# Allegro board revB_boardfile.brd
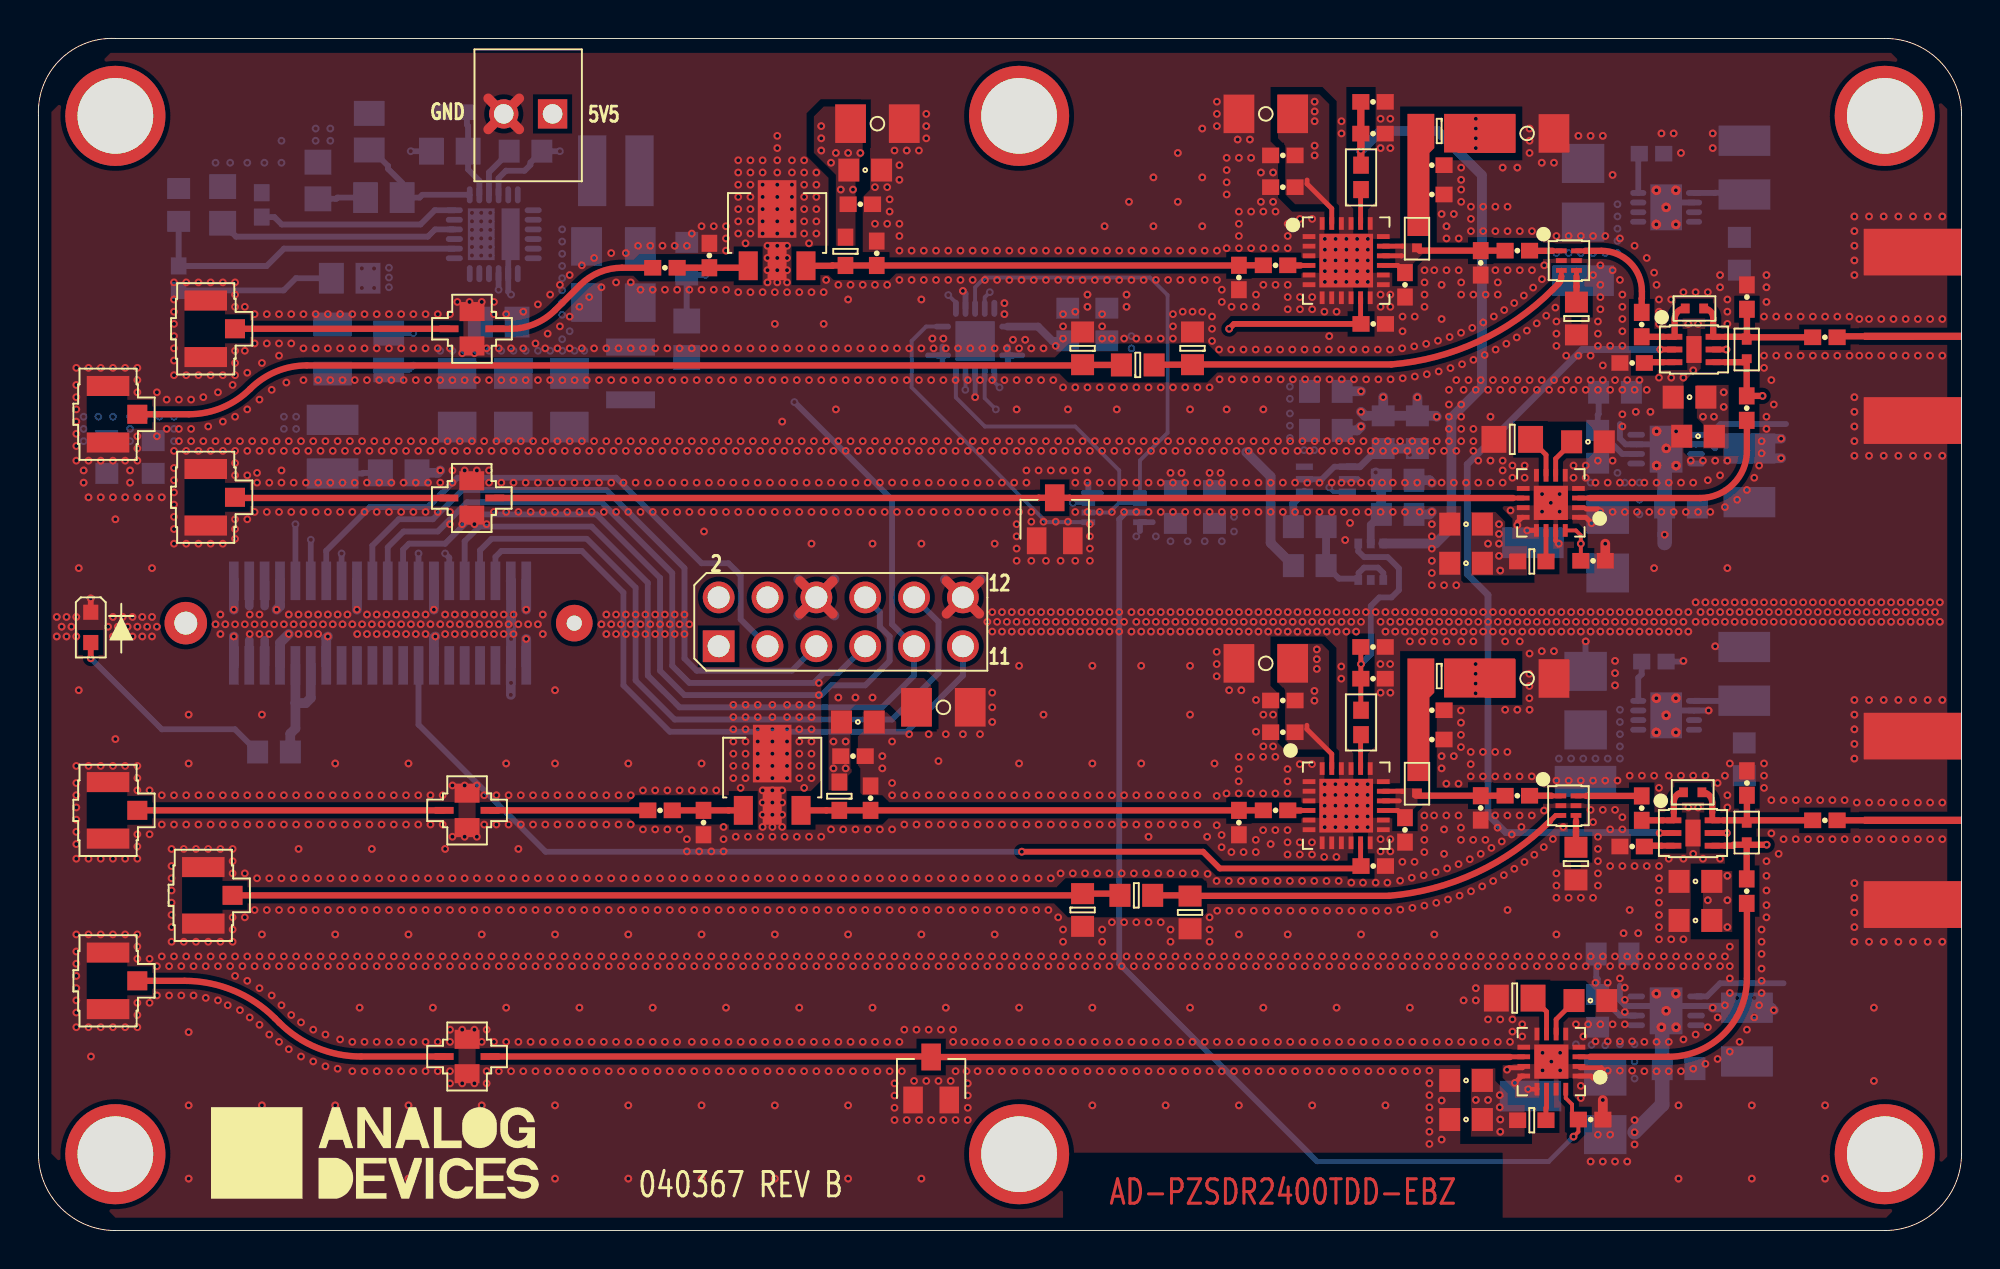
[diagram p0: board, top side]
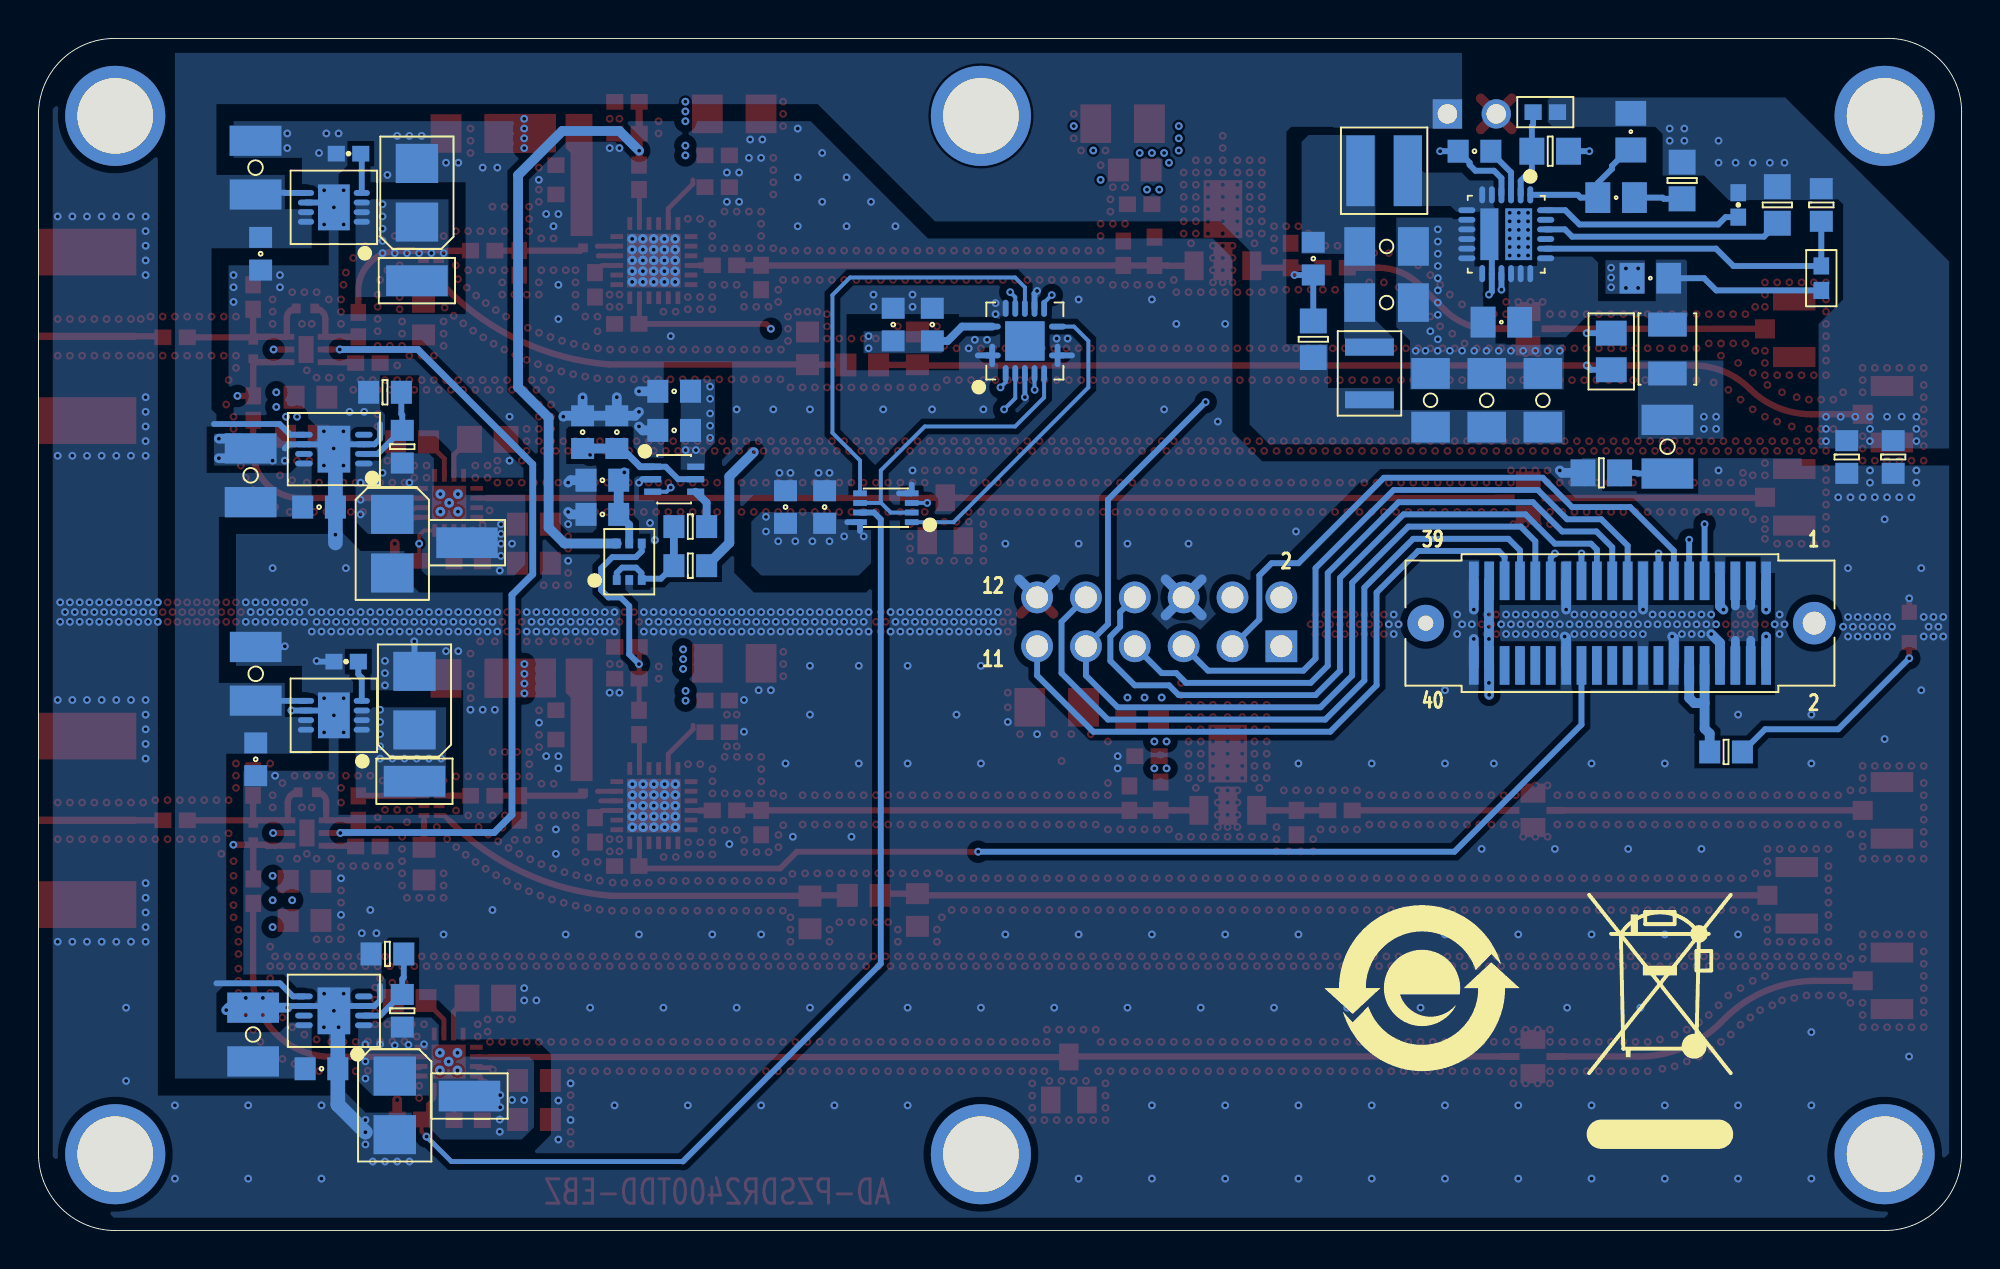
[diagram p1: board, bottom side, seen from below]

Outline 99.99 x 61.99 mm; copper layers: TOP, L2_GND, L3_PWR, BOTTOM. Coordinates in mm from the lower left corner of the outline.
Outline path: 0,58 0,4 arc(1.17,1.17) 4,0 96,0 arc(98.82,1.17) 99.99,4 99.99,58 arc(98.84,60.84) 96,61.99 4,61.99 arc(1.12,60.88) 0,58

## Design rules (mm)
net group RF_GPIO0_5V: nets RF_GPIO0_5V UNNAMED_2_ADHMC921_I79_VEN
net group RF_GPIO1_5V: nets RF_GPIO1_5V UNNAMED_3_ADHMC921_I94_VEN

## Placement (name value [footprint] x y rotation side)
AMP1  HK-1-G  [CNTP1206]  80.32 49.4 0 bottom
AMP2  HK-1-G  [CNTP1206]  80.44 23.37 0 bottom
C1  8200PF  [C0603]  80.7 11.96 0 top
C2  1000pF  [C0402]  83.87 56 0 bottom
C3  8200PF  [C0603]  80.57 41.02 0 top
C4  1UF  [C0603]  61.15 37.63 90 bottom
C5  2.2pF  [C0402]  32.32 21.85 0 top
C6  1.3pF  [C0402]  34.58 21.22 270 top
C7  10uF  [C1206]  47.05 27.21 0 top
C8  10000pF  [C0603]  42.61 26.45 0 top
C9  100PF  [C0402]  42.35 24.67 0 top
C10  1UF  [C0603]  74.23 7.81 180 top
C11  10000pF  [C0603]  74.23 5.77 180 top
C12  2pF  [C0402]  43.27 22.49 90 top
C13  3.3pF  [C0402]  62.42 21.22 270 top
C14  100PF  [C0402]  80.71 5.77 0 top
C15  2.7pF  [C0402]  64.32 21.85 0 top
C16  2.2uF  [C1206]  63.82 29.5 0 top
C17  1000pF  [C0402]  64.71 27.57 0 top
C18  100PF  [C0402]  64.71 25.92 0 top
C19  4.7uF  [C0805H60]  16.18 49.53 0 bottom
C20  22uF  [C1210]  88.71 55.28 90 bottom
C21  22uF  [C1210]  88.96 39.28 90 bottom
C22  1UF  [C0603]  88.44 50.8 270 bottom
C23  1UF  [C0603]  85.41 37.63 180 bottom
C24  100PF  [C0402]  69.4 18.96 0 top
C25  1000pF  [C0402]  69.39 30.35 0 top
C26  10uF  [C3528]  80.32 53.97 90 bottom
C27  10uF  [C3528]  81.6 35.72 270 bottom
C28  100PF  [C0402]  69.39 28.7 0 top
C29  4pF  [C0402]  71.06 20.84 270 top
C30  2.2uF  [C1206]  77.41 28.71 0 top
C31  1000pF  [C0402]  72.45 27.06 0 top
C32  100PF  [C0402]  72.45 25.53 0 top
C33  1.5pF  [C0402]  74.99 21.98 270 top
C34  100PF  [C0402]  76.9 22.61 0 top
C35  330pF  [C0402]  83.36 21.97 270 top
C36  1.8PF  [C0402]  82.87 19.97 180 top
C37  1UF  [C0603]  86.16 16.13 180 top
C38  10000pF  [C0603]  86.16 18.16 180 top
C39  330pF  [C0402]  88.83 17.65 90 top
C40  0.7pF  [C0402]  88.84 23.27 90 top
C41  330pF  [C0402]  92.89 21.33 0 top
C42  2.2pF  [C0402]  32.57 50.07 0 top
C43  1.3pF  [C0402]  34.89 50.71 90 top
C44  10uF  [C1206]  43.62 57.56 0 top
C45  10000pF  [C0603]  42.99 55.15 0 top
C46  100PF  [C0402]  42.73 53.37 0 top
C47  1UF  [C0603]  74.23 36.74 180 top
C48  10000pF  [C0603]  74.23 34.7 180 top
C49  2pF  [C0402]  43.59 50.82 90 top
C50  3.3pF  [C0402]  62.42 49.56 270 top
C51  100PF  [C0402]  80.83 34.83 0 top
C52  2.7pF  [C0402]  64.32 50.2 0 top
C53  2.2uF  [C1206]  63.82 58.07 0 top
C54  1000pF  [C0402]  64.71 55.91 0 top
C55  100PF  [C0402]  64.71 54.26 0 top
C56  100PF  [C0402]  69.4 47.15 0 top
C57  1000pF  [C0402]  69.39 58.7 0 top
C58  100PF  [C0402]  69.39 57.05 0 top
C59  4pF  [C0402]  71.06 49.18 270 top
C60  2.2uF  [C1206]  77.41 57.06 0 top
C61  1000pF  [C0402]  72.45 55.41 0 top
C62  100PF  [C0402]  72.45 53.88 0 top
C63  1.5pF  [C0402]  74.99 50.33 270 top
C64  100PF  [C0402]  76.9 50.96 0 top
C65  330pF  [C0402]  83.36 47.11 270 top
C66  1.8PF  [C0402]  82.87 45.12 180 top
C67  1UF  [C0603]  86.3 41.31 180 top
C68  10000pF  [C0603]  85.85 43.34 180 top
C69  330pF  [C0402]  88.83 42.77 90 top
C70  10000pF  [C0603]  59.12 37.63 90 bottom
C71  330pF  [C0402]  92.89 46.45 0 top
C72  22uF  [C1210]  88.7 28.95 90 bottom
C73  22uF  [C1210]  88.84 10.19 90 bottom
C74  1UF  [C0603]  88.7 24.51 270 bottom
C75  1UF  [C0603]  85.28 8.42 180 bottom
C76  1000pF  [C0402]  84 29.59 0 bottom
C77  10uF  [C3528]  80.44 27.56 90 bottom
C78  10uF  [C3528]  81.47 6.51 270 bottom
C79  4.7uF  [C0805H60]  23.93 47.24 0 bottom
C80  TBD0402  [C0402]  11.61 53.34 90 bottom
C81  0.1uF  [C0805H53]  18.21 45.72 270 bottom
C82  1UF  [C0603]  25.33 56.13 180 bottom
C83  470pF  [C0603]  33.71 50.54 270 bottom
C84  0.015UF  [C0805]  17.96 53.72 180 bottom
C85  47UF  [C1206]  29.9 51.18 180 bottom
C86  33pF  [C0805]  17.2 57.15 90 bottom
C87  47UF  [C1206]  29.9 48.26 180 bottom
C88  47UF  [C1206]  21.77 43.18 90 bottom
C89  47UF  [C1206]  24.69 43.18 90 bottom
C90  47UF  [C1206]  27.61 43.18 90 bottom
C91  0.7pF  [C0402]  88.84 48.55 90 top
C92  22uF  [C1210]  15.29 40.76 270 bottom
C93  1UF  [C0603]  71.7 41.52 270 bottom
C94  10000pF  [C0603]  69.92 41.52 270 bottom
C95  1UF  [C0603]  66.94 43.64 0 bottom
C96  10000pF  [C0603]  66.94 41.61 0 bottom
C97  1UF  [C0603]  70.67 39.02 0 bottom
C98  10000pF  [C0603]  70.67 37.24 0 bottom
C101  1UF  [C0603]  55.55 47.11 90 bottom
C102  10000pF  [C0603]  53.52 47.11 90 bottom
D1  SMP1330-005LF  [SOT23]  46.42 7.91 0 top
D2  SMP1330-005LF  [SOT23]  52.84 36.99 0 top
DS1  LG Q971  [LED0603-2]  2.72 31.37 270 top
FL1  2400-2500MEGHZ  [FL0805_A]  22.54 46.9 180 top
FL2  2400-2500MEGHZ  [FL0805_A]  22.53 38.1 0 top
FL3  2400-2500MEGHZ  [FL0805_A]  22.29 21.85 180 top
FL4  2400-2500MEGHZ  [FL0805_A]  22.29 9.05 0 top
L1  0.47uH  [L1210H67]  15.29 45.84 90 bottom
L2  15nH  [L0603]  41.64 22.59 90 top
L3  15nH  [L0603]  77.65 5.74 180 top
L4  13nH  [L0402-3]  71.68 23.24 90 top
L5  2nH  [L0402-3]  86.02 22.79 0 top
L6  3.3nH  [L0402-3]  88.83 20.7 90 top
L7  15nH  [L0603]  41.96 50.92 90 top
L8  15nH  [L0603]  77.65 34.8 180 top
L9  13nH  [L0402-3]  71.68 51.58 90 top
L10  2nH  [L0402-3]  86.11 47.95 0 top
L11  3.3nH  [L0402-3]  88.83 45.82 90 top
L12  3.3uH  [LSMSQ157H83]  30.02 55.12 0 bottom
L13  2.2uH  [LSML126W90H59]  30.79 44.57 270 bottom
LNA1  HK-1-G  [CNTP1206]  77.71 35.77 0 bottom
LNA2  HK-1-G  [CNTP1206]  77.58 6.99 0 bottom
NOREF  -  []  45.91 83.98 0 top
NOREF#2  -  []  -30.21 -73.27 0 top
NOREF#3  -  []  0 67.43 0 top
NOREF#4  -  [unnamed#2]  4 57.97 0 top
NOREF#5  -  []  -76.66 -230 0 top
NOREF#6  -  []  -76.65 -230 0 top
NOREF#7  -  []  17.52 4.03 0 top
NOREF#8  -  []  -38.14 158.35 0 top
NOREF#9  -  [unnamed#2]  96 3.97 0 top
NOREF#10  -  []  105.59 0 0 top
NOREF#11  -  []  95.31 -30.07 0 top
NOREF#12  -  []  99.01 60.65 0 top
NOREF#13  -  [unnamed#2]  50.99 3.97 0 top
NOREF#14  -  [unnamed#2]  96 57.97 0 top
NOREF#15  -  []  99.99 67.7 0 top
NOREF#16  -  []  105.65 61.99 0 top
NOREF#17  -  [unnamed#2]  4 3.97 0 top
NOREF#18  -  [unnamed#2]  50.99 57.97 0 top
NOREF#19  -  []  -89.23 -242.57 0 top
NOREF#20  -  []  28.05 12.61 180 bottom
NOREF#21  -  []  6.41 21.14 180 bottom
P1  TSW-106-08-G-D  [CNBERG2X6H330LD36]  35.37 30.39 0 top
P2  61082-041402LF  [CNFCI61082-041402]  17.76 31.59 0 bottom
P3  22-23-2021  [CNHDR1X2H430]  26.73 58.07 180 top
R1  15  [R0805]  76.76 12.09 180 top
R2  15  [R0805]  76.63 41.15 180 top
R3  1  [R0805]  18.73 39.4 0 bottom
R4  402  [R0402]  68.77 54.77 270 top
R5  150  [R0603]  54.29 16.67 270 top
R6  37.4  [R0603]  57.09 17.43 0 top
R7  150  [R0603]  59.88 16.54 270 top
R8  402  [R0402]  68.77 26.42 270 top
R9  49.9  [R0603]  79.95 19.08 270 top
R10  13K  [R0603]  81.98 43.59 180 bottom
R11  0  [R0603]  3.55 40.23 270 bottom
R12  40.2K  [R0603]  81.08 40.76 270 bottom
R13  150  [R0603]  54.29 45.88 90 top
R14  37.4  [R0603]  57.16 45.02 0 top
R15  300  [R0603]  12.24 24.89 180 bottom
R16  150  [R0603]  60.01 45.88 90 top
R18  49.9  [R0603]  79.97 47.43 270 top
R19  13K  [R0603]  81.85 14.38 180 bottom
R20  40.2K  [R0603]  81.08 11.43 270 bottom
R21  1.5K  [R0603]  7.29 53.34 270 bottom
R22  76.8K  [R0805]  9.58 53.34 90 bottom
R23  10.7K  [R0402]  7.29 49.53 90 bottom
R24  82.5K  [R0805]  21.39 56.13 180 bottom
R25  11K  [R0402]  21.64 58.16 0 bottom
R26  4.02K  [R0805]  14.53 54.61 90 bottom
R27  4.02K  [R0805]  33.71 46.35 90 bottom
R28  0  [R0603]  66.1 36.61 0 bottom
R29  0  [R0603]  66.1 34.58 180 bottom
R30  0  [R0603]  72.83 57.18 180 top
R31  0  [R0603]  72.83 28.84 180 top
R32  0  [R0603]  5.97 40.23 270 bottom
RF_IO1  JOHNSON142-0701-851  [CNJOHNSON142-0701-851]  97.45 46.5 0 top
RF_IO2  JOHNSON142-0701-851  [CNJOHNSON142-0701-851]  97.45 21.33 0 top
RX1_A  U.FL-R-SMT-1(01)  [CNHIROSE-U_FL-R-SMT-1]  8.7 38.13 90 top
RX2_A  U.FL-R-SMT-1(01)  [CNHIROSE-U_FL-R-SMT-1]  3.62 12.99 90 top
T1  DCW-30-272+  [TSML63W31H29]  79.55 22.1 270 top
T2  DCW-30-272+  [TSML63W31H29]  79.58 50.44 270 top
TX1_A  U.FL-R-SMT-1(01)  [CNHIROSE-U_FL-R-SMT-1]  8.7 46.9 90 top
TX1MON  U.FL-R-SMT-1(01)  [CNHIROSE-U_FL-R-SMT-1]  3.62 42.45 90 top
TX2_A  U.FL-R-SMT-1(01)  [CNHIROSE-U_FL-R-SMT-1]  3.62 21.85 90 top
TX2MON  U.FL-R-SMT-1(01)  [CNHIROSE-U_FL-R-SMT-1]  8.57 17.43 90 top
U1  ADM7171ACPZ-5.0  [DFN8_3X3_PAD2_38X1_64]  84.63 53.21 90 bottom
U2  HMC669LP3E  [LP3]  78.67 8.79 90 top
U3  ADP7104ACPZ  [QFN8_3X3_PAD2_44X1_7]  84.63 40.64 90 bottom
U4  74LVC1T45GW,125  [SOT363]  66.94 39.07 270 bottom
U5  HMC921LP4E  [LP4]  68 22.1 270 top
U6  HMC546LP2E  [LP2]  86.03 20.67 270 top
U7  HMC669LP3E  [LP3]  78.64 37.84 90 top
U8  HMC921LP4E  [LP4]  68 50.44 270 top
U9  ADL5324ARKZ  [SOT-89]  38.15 24.08 0 top
U10  ADL5324ARKZ  [SOT-89]  38.41 52.4 0 top
U11  HMC546LP2E  [LP2]  86.08 45.82 270 top
U12  ADM7171ACPZ-5.0  [DFN8_3X3_PAD2_38X1_64]  84.63 26.79 90 bottom
U13  ADP7104ACPZ  [QFN8_3X3_PAD2_44X1_7]  84.63 11.43 90 bottom
U14  ADP2384ACPZN  [QFN24_4X4_2PAD]  23.67 51.81 0 bottom
U15  NC7WV16P6X  [SC70]  69.28 34.78 180 bottom
U16  SN74LV4T125RGYR  [QFN14_3_5X3_5_PAD2_05X2_05]  48.7 46.26 180 bottom
U30  NL27WZ08USG  [US8]  55.93 37.59 90 bottom

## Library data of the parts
AMP1 AMP2 LNA1 LNA2 = CNTP1P: User Part Number: UPN; alternate symbols: (CNBANANA_ALT); part number: CNTP1P_SM-HK-1-G,E012928,CNTP1206
C1 C3 = CAP: User Part Number: UPN; Tolerance: 5; part number: CAP_SM-8200PF,50V,5,E000433,C0603; tolerance: 5; signal model: DEFAULT_CAPACITOR_100000pF_1_2
C2 C17 C25 = CAP: User Part Number: UPN; Tolerance: 5; part number: CAP_SM-1000PF,25V,5,E017843,C0402; tolerance: 5; signal model: DEFAULT_CAPACITOR_100000pF_1_2
C4 C37 C47 C67 C74 C75 C82 C93 C95 C97 C101 = CAP: User Part Number: UPN; Tolerance: 10; part number: CAP_SM-1UF,25V,10,E006992,C0603; tolerance: 10
C5 C42 = CAP: User Part Number: UPN; Tolerance: 0.1pF; part number: CAP_SM-2.2PF,50V,0.1PF,E020664,C0402; tolerance: 0.1pF
C6 C43 = CAP: User Part Number: UPN; Tolerance: 0.25pF; part number: CAP_SM-1.3PF,50V,0.25PF,E010801,C0402; tolerance: 0.25pF
C7 C44 = CAP: User Part Number: UPN; Tolerance: 10; part number: CAP_SM-10UF,10V,10,E011047,C1206; tolerance: 10
C8 C11 = CAP: User Part Number: UPN; Tolerance: 10; part number: CAP_SM-10000PF,25V,10,E012078,C0603; tolerance: 10; signal model: DEFAULT_CAPACITOR_100000pF_1_2
C9 C14 C18 C24 = CAP: User Part Number: UPN; Tolerance: 5; part number: CAP_SM-100PF,50V,5,E023843,C0402; tolerance: 5; signal model: DEFAULT_CAPACITOR_100000pF_1_2
C10 C22 C23 = CAP: User Part Number: UPN; Tolerance: 10; part number: CAP_SM-1UF,25V,10,E006992,C0603; tolerance: 10; signal model: DEFAULT_CAPACITOR_100000pF_1_2
C12 = CAP: User Part Number: UPN; Tolerance: +/-0.25pF; part number: CAP_SM-2PF,50V,+/-0.25PF,E012548,C0402; tolerance: +/-0.25pF; signal model: DEFAULT_CAPACITOR_100000pF_1_2
C13 = CAP: User Part Number: UPN; Tolerance: +/-0.25pF; part number: CAP_SM-3.3PF,50V,+/-0.25PF,E012551,C0402; tolerance: +/-0.25pF; signal model: DEFAULT_CAPACITOR_100000pF_1_2
C15 = CAP: User Part Number: UPN; Tolerance: +/- 0.1pF; part number: CAP_SM-2.7PF,50V,+/- 0.1PF,E011097,C0402; tolerance: +/- 0.1pF; signal model: DEFAULT_CAPACITOR_100000pF_1_2
C16 = CAP: User Part Number: UPN; Tolerance: 5; part number: CAP_SM-2.2UF,10V,5,E018907,C1206; tolerance: 5; signal model: DEFAULT_CAPACITOR_100000pF_1_2
C19 = CAP: User Part Number: UPN; Tolerance: 20; part number: CAP_SM-4.7UF,25V,20,E020124,C0805H60; tolerance: 20; signal model: DEFAULT_CAPACITOR_100000pF_1_2
C20 C21 = CAP: Tolerance: 10; User Part Number: UPN; part number: CAP_SM-22UF,25V,10,E010936,C1210; tolerance: 10; signal model: DEFAULT_CAPACITOR_100000pF_1_2
C26 C27 C77 C78 = CAPP: Tolerance: 10; User Part Number: UPN; part number: CAPP_SM-10UF,25V,10,E014942,C3528; tolerance: 10
C28 C32 C34 C46 C51 C55 C56 C58 C62 C64 = CAP: User Part Number: UPN; Tolerance: 5; part number: CAP_SM-100PF,50V,5,E023843,C0402; tolerance: 5
C29 C59 = CAP: User Part Number: UPN; Tolerance: +/- 0.1pF; part number: CAP_SM-4PF,50V,+/- 0.1PF,E011106,C0402; tolerance: +/- 0.1pF
C30 C53 C60 = CAP: User Part Number: UPN; Tolerance: 5; part number: CAP_SM-2.2UF,10V,5,E018907,C1206; tolerance: 5
C31 C54 C57 C61 C76 = CAP: User Part Number: UPN; Tolerance: 5; part number: CAP_SM-1000PF,25V,5,E017843,C0402; tolerance: 5
C33 C63 = CAP: User Part Number: UPN; Tolerance: +/-0.25pF; part number: CAP_SM-1.5PF,50V,+/-0.25PF,E012549,C0402; tolerance: +/-0.25pF
C35 C39 C65 C69 C71 = CAP: User Part Number: UPN; Tolerance: 10; part number: CAP_SM-330PF,50V,10,E012647,C0402; tolerance: 10
C36 C66 = CAP: User Part Number: UPN; Tolerance: 0.25PF; part number: CAP_SM-1.8PF,50V,0.25PF,E000263,C0402; tolerance: 0.25PF
C38 C45 C48 C68 C70 C94 C96 C98 C102 = CAP: User Part Number: UPN; Tolerance: 10; part number: CAP_SM-10000PF,25V,10,E012078,C0603; tolerance: 10
C40 = CAP: User Part Number: UPN; Tolerance: 5; part number: CAP_SM-0.7PF,25V,5,E012595,C0402; tolerance: 5; signal model: DEFAULT_CAPACITOR_100000pF_1_2
C41 = CAP: User Part Number: UPN; Tolerance: 10; part number: CAP_SM-330PF,50V,10,E012647,C0402; tolerance: 10; signal model: DEFAULT_CAPACITOR_100000pF_1_2
C49 = CAP: User Part Number: UPN; Tolerance: +/-0.25pF; part number: CAP_SM-2PF,50V,+/-0.25PF,E012548,C0402; tolerance: +/-0.25pF
C50 = CAP: User Part Number: UPN; Tolerance: +/-0.25pF; part number: CAP_SM-3.3PF,50V,+/-0.25PF,E012551,C0402; tolerance: +/-0.25pF
C52 = CAP: User Part Number: UPN; Tolerance: +/- 0.1pF; part number: CAP_SM-2.7PF,50V,+/- 0.1PF,E011097,C0402; tolerance: +/- 0.1pF
C72 C73 C92 = CAP: Tolerance: 10; User Part Number: UPN; part number: CAP_SM-22UF,25V,10,E010936,C1210; tolerance: 10
C79 = CAP: User Part Number: UPN; Tolerance: 20; part number: CAP_SM-4.7UF,25V,20,E020124,C0805H60; tolerance: 20
C80 = CAP: User Part Number: UPN; part number: CAP_SM-TBD0402,TBD0402,TBD0402,E000381,C0402
C81 = CAP: User Part Number: UPN; Tolerance: 10; part number: CAP_SM-0.1UF,50V,10,E010137,C0805H53; tolerance: 10
C83 = CAP: User Part Number: UPN; Tolerance: 5; part number: CAP_SM-470PF,25V,5,E017265,C0603; tolerance: 5
C84 = CAP: User Part Number: UPN; Tolerance: 10; part number: CAP_SM-0.015UF,50V,10,E000449,C0805; tolerance: 10
C85 C87-C90 = CAP: User Part Number: UPN; Tolerance: 20; part number: CAP_SM-47UF,6.3V,20,E006154,C1206; tolerance: 20
C86 = CAP: User Part Number: UPN; Tolerance: 5; part number: CAP_SM-33PF,50V,5,E012492,C0805; tolerance: 5
C91 = CAP: User Part Number: UPN; Tolerance: 5; part number: CAP_SM-0.7PF,25V,5,E012595,C0402; tolerance: 5
D1 D2 = DIO3P_V3: Tolerance: N/A; User Part Number: UPN; part number: DIO3P_V3_SM-SMP1330-005LF,20V,N/A,E022992,SOT23; tolerance: N/A
DS1 = DIOLED: User Part Number: UPN; Tolerance: N/A; part number: DIOLED_SM-LG Q971,2.2V,N/A,E017871,LED0603-2; tolerance: N/A
FL1-FL4 = FLTRBP4P_V2: User Part Number: UPN; part number: FLTRBP4P_V2_SM-2400-2500MEGHZ,E023131,FL0805_A
L1 = IND: Tolerance: 30; User Part Number: UPN; alternate symbols: (L0402-2,L0603_ALT,L1008L_ALT); part number: IND_SM-0.47UH,30,E018627,L1210H67; tolerance: 30
L2 L3 L7 L8 = IND: User Part Number: UPN; Tolerance: 2; alternate symbols: (L0402-2,L0603_ALT,L1008L_ALT); part number: IND_SM-15NH,2,E016779,L0603; tolerance: 2
L4 L9 = IND: User Part Number: UPN; Tolerance: 2; alternate symbols: (L0402-2,L0603_ALT,L1008L_ALT); part number: IND_SM-13NH,2,E023162,L0402-3; tolerance: 2
L5 L10 = IND: User Part Number: UPN; Tolerance: 0.3nH; alternate symbols: (L0402-2,L0603_ALT,L1008L_ALT); part number: IND_SM-2NH,0.3NH,E019382,L0402-3; tolerance: 0.3nH
L6 L11 = IND: User Part Number: UPN; Tolerance: 0.2nH; alternate symbols: (L0402-2,L0603_ALT,L1008L_ALT); part number: IND_SM-3.3NH,0.2NH,E023163,L0402-3; tolerance: 0.2nH
L12 = IND: Tolerance: 20; User Part Number: UPN; alternate symbols: (L0402-2,L0603_ALT,L1008L_ALT); part number: IND_SM-3.3UH,20,E013588,LSMSQ157H83; tolerance: 20
L13 = IND: Tolerance: 20; User Part Number: UPN; alternate symbols: (L0402-2,L0603_ALT,L1008L_ALT); part number: IND_SM-2.2UH,20,E018625,LSML126W90H59; tolerance: 20
P1 = CN12P: User Part Number: UPN; part number: CN12P_TH-TSW-106-08-G-D,E000735,CNBERG2X6H330LD36
P2 = CN40P: User Part Number: UPN; part number: CN40P_SM-61082-041402LF,E022581,CNFCI61082-041402
P3 = CN2P: User Part Number: UPN; part number: CN2P_TH-22-23-2021,E018594,CNHDR1X2H430
R1 R2 = RES: User Part Number: UPN; Tolerance: 0.5; part number: RES_SM-15,E003975,1/10W,0.5,R0805; tolerance: 0.5
R3 = RES: User Part Number: UPN; part number: RES_SM-1,E003556,1/10W,1,R0805
R4 R8 = RES: User Part Number: UPN; Tolerance: 1; part number: RES_SM-402,E004027,1/16W,1,R0402; tolerance: 1; signal model: DEFAULT_RESISTOR_0.001OHM_1_2
R5 R7 = RES: User Part Number: UPN; Tolerance: 1; part number: RES_SM-150,E003691,1/10W,1,R0603; tolerance: 1
R6 = RES: User Part Number: UPN; Tolerance: 1; part number: RES_SM-37.4,E003933,1/10W,1,R0603; tolerance: 1
R9 R18 = RES: User Part Number: UPN; Tolerance: 1; part number: RES_SM-49.9,E003673,1/10W,1,R0603; tolerance: 1
R10 R19 = RES: User Part Number: UPN; Tolerance: 1; part number: RES_SM-13K,E020173,1/10W,1,R0603; tolerance: 1
R11 R28-R32 = RES: User Part Number: UPN; Tolerance: 1; part number: RES_SM-0,E004207,1/16W,1,R0603; tolerance: 1
R12 R20 = RES: User Part Number: UPN; Tolerance: 1; part number: RES_SM-40.2K,E013312,1/10W,1,R0603; tolerance: 1
R13 = RES: User Part Number: UPN; Tolerance: 1; part number: RES_SM-150,E003691,1/10W,1,R0603; tolerance: 1; signal model: DEFAULT_RESISTOR_100.000000OHM_1_2
R14 = RES: User Part Number: UPN; Tolerance: 1; part number: RES_SM-37.4,E003933,1/10W,1,R0603; tolerance: 1; signal model: DEFAULT_RESISTOR_100.000000OHM_1_2
R15 = RES: User Part Number: UPN; Tolerance: 1; part number: RES_SM-300,E016618,1/16W,1,R0603; tolerance: 1
R16 = RES: User Part Number: UPN; Tolerance: 1; part number: RES_SM-150,E003691,1/10W,1,R0603; tolerance: 1; signal model: DEFAULT_RESISTOR_0.001OHM_1_2
R21 = RES: User Part Number: UPN; Tolerance: 1; part number: RES_SM-1.5K,E003704,1/16W,1,R0603; tolerance: 1
R22 = RES: User Part Number: UPN; Tolerance: 1; part number: RES_SM-76.8K,E014296,1/8W,1,R0805; tolerance: 1
R23 = RES: User Part Number: UPN; Tolerance: 1; part number: RES_SM-10.7K,E019637,1/16W,1,R0402; tolerance: 1
R24 = RES: User Part Number: UPN; Tolerance: 1; part number: RES_SM-82.5K,E014295,1/8W,1,R0805; tolerance: 1
R25 = RES: User Part Number: UPN; Tolerance: 1; part number: RES_SM-11K,E015614,1/10W,1,R0402; tolerance: 1
R26 R27 = RES: User Part Number: UPN; Tolerance: 1; part number: RES_SM-4.02K,E003522,1/8W,1,R0805; tolerance: 1
RF_IO1 RF_IO2 = CNBNC5P: User Part Number: UPN; alternate symbols: (CNAMPHENOL132255-11_ALT); part number: CNBNC5P_SM-JOHNSON142-0701-851,E000923,CNJOHNSON142-0701-851
RX1_A RX2_A TX1_A TX1MON TX2_A TX2MON = CNBNC3P: User Part Number: UPN; alternate symbols: (CNROS32K243-40ML5_ALT); part number: CNBNC3P_SM-U.FL-R-SMT-1(01),E022198,CNHIROSE-U_FL-R-SMT-1
T1 T2 = XFMRCOUPLER_V4: User Part Number: UPN; part number: XFMRCOUPLER_V4_SM-DCW-30-272+,E022977,TSML63W31H29
U1 U12 = ADM7171: User Part Number: UPN; part number: ADM7171_SM-ADM7171ACPZ-5.0,E022768,DFN8_3X3_PAD2_38X1_64
U2 U7 = ADHMC669: User Part Number: UPN; part number: ADHMC669_SM-HMC669LP3E,E022979,LP3
U3 U13 = ADP7104: User Part Number: UPN; part number: ADP7104_SM-ADP7104ACPZ,E017004,QFN8_3X3_PAD2_44X1_7
U4 = 7445_V2: User Part Number: UPN; part number: 7445_V2_SM-74LVC1T45GW,125,E023100,SOT363
U5 U8 = ADHMC921: User Part Number: UPN; part number: ADHMC921_SM-HMC921LP4E,E022761,LP4
U6 U11 = ADHMC546: User Part Number: UPN; part number: ADHMC546_SM-HMC546LP2E,E022963,LP2
U9 U10 = ADL5324: User Part Number: UPN; part number: ADL5324_SM-ADL5324ARKZ,E016769,SOT-89
U14 = ADP238X: User Part Number: UPN; part number: ADP238X_SM-ADP2384ACPZN,E012984,QFN24_4X4_2PAD
U15 = NC7WZ17P6X: User Part Number: UPN; part number: NC7WZ17P6X_SM-NC7WV16P6X,E010997,SC70
U16 = 74125_V7: User Part Number: UPN; part number: 74125_V7_SM-SN74LV4T125RGYR,E023102,QFN14_3_5X3_5_PAD2_05X2_05
U30 = NL27WZ08: User Part Number: UPN; part number: NL27WZ08_SM-NL27WZ08USG,E007397,US8

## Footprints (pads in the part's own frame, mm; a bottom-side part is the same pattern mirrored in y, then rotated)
C0402
  rect 0.889x0.813 smd: 1(-0.635,0) 2(0.635,0)
C0603
  rect 1.092x1.194 smd: 1(-0.851,0) 2(0.851,0)
C0805
  rect 1.295x1.6 smd: 1(-0.953,0) 2(0.953,0)
C0805H53
  rect 1.295x1.6 smd: 1(-0.953,0) 2(0.953,0)
C0805H60
  rect 1.295x1.6 smd: 1(-0.953,0) 2(0.953,0)
C1206
  rect 1.6x2.007 smd: 1(-1.397,0) 2(1.397,0)
C1210
  rect 1.575x2.692 smd: 1(-1.397,0) 2(1.397,0)
C3528
  rect 2.032x2.21 smd: N(1.524,0) P(-1.524,0)
CNBERG2X6H330LD36
  rect 1.651x1.651 hole 1.143: 1(0,0)
  round 1.651 hole 1.143: 2(0,2.54) 3(2.54,0) 4(2.54,2.54) 5(5.08,0) 6(5.08,2.54) 7(7.62,0) 8(7.62,2.54) 9(10.16,0) 10(10.16,2.54) 11(12.7,0) 12(12.7,2.54)
CNFCI61082-041402
  round 2.21 hole 1.194 unplated: (-10.1,0)
  round 1.905 hole 0.787 unplated: (10.1,0)
  rect 0.508x2.007 smd: 1(-7.6,-2.2) 2(-7.6,2.2) 3(-6.8,-2.2) 4(-6.8,2.2) 5(-6,-2.2) 6(-6,2.2) 7(-5.2,-2.2) 8(-5.2,2.2) 9(-4.4,-2.2) 10(-4.4,2.2) 11(-3.6,-2.2) 12(-3.6,2.2) 13(-2.8,-2.2) 14(-2.8,2.2) 15(-2,-2.2) 16(-2,2.2) 17(-1.2,-2.2) 18(-1.2,2.2) 19(-0.4,-2.2) 20(-0.4,2.2) 21(0.4,-2.2) 22(0.4,2.2) 23(1.2,-2.2) 24(1.2,2.2) 25(2,-2.2) 26(2,2.2) 27(2.8,-2.2) 28(2.8,2.2) 29(3.6,-2.2) 30(3.6,2.2) 31(4.4,-2.2) 32(4.4,2.2) 33(5.2,-2.2) 34(5.2,2.2) 35(6,-2.2) 36(6,2.2) 37(6.8,-2.2) 38(6.8,2.2) 39(7.6,-2.2) 40(7.6,2.2)
CNHDR1X2H430
  rect 1.524x1.524 hole 1.016: 1(0,0)
  round 1.524 hole 1.016: 2(2.54,0)
CNHIROSE-U_FL-R-SMT-1
  rect 0.991x1.041 smd: 1(0,-1.521)
  rect 1.041x2.21 smd: 2(-1.471,0) 3(1.471,0)
CNJOHNSON142-0701-851
  rect 5.08x0.381 smd: 1(0,0)
  rect 5.08x2.413 smd: 2(0,4.381) 3(0,4.381) 4(0,-4.381) 5(0,-4.381)
CNTP1206
  rect 3.2x1.6 smd: 1(0,0)
DFN8_3X3_PAD2_38X1_64
  oval 0.305x0.838 smd: 1(-0.75,-1.45) 2(-0.25,-1.45) 3(0.25,-1.45) 4(0.75,-1.45) 5(0.75,1.45) 6(0.25,1.45) 7(-0.25,1.45) 8(-0.75,1.45)
  rect 2.388x1.651 smd: PAD(0,0)
FL0805_A
  rect 1.295x0.991 smd: 1(0,-0.895) 3(0,0.895)
  rect 0.991x0.356 smd: 2(-1.195,0) 4(1.195,0)
L0402-3
  rect 0.457x0.508 smd: 1(-0.479,0) 2(0.479,0)
L0603
  rect 0.889x0.813 smd: 1(-0.737,0) 2(0.737,0)
L1210H67
  rect 1.245x2.007 smd: 1(-1.272,0) 2(1.272,0)
LED0603-2
  rect 0.787x0.787 smd: A(0.787,0) C(-0.787,0)
LP2
  rect 0.305x0.787 smd: 1(-0.66,-0.998) 2(0,-0.998) 3(0.66,-0.998) 4(0.66,1.001) 5(0,1.001) 6(-0.66,1.001)
  rect 1.397x0.787 smd: PAD(0,0)
LP3
  rect 0.254x0.66 smd: 1(-0.751,-1.435) 2(-0.25,-1.435) 3(0.25,-1.435) 4(0.751,-1.435) 9(0.751,1.435) 10(0.25,1.435) 11(-0.25,1.435) 12(-0.751,1.435)
  rect 0.66x0.254 smd: 5(1.435,-0.751) 6(1.435,-0.25) 7(1.435,0.25) 8(1.435,0.751) 13(-1.435,0.751) 14(-1.435,0.25) 15(-1.435,-0.25) 16(-1.435,-0.751)
  rect 1.778x1.778 smd: PAD(0,0)
LP4
  rect 0.254x0.66 smd: 1(-1.251,-1.93) 2(-0.751,-1.93) 3(-0.25,-1.93) 4(0.25,-1.93) 5(0.751,-1.93) 6(1.251,-1.93) 13(1.251,1.93) 14(0.751,1.93) 15(0.25,1.93) 16(-0.25,1.93) 17(-0.751,1.93) 18(-1.251,1.93)
  rect 0.66x0.254 smd: 7(1.93,-1.251) 8(1.93,-0.751) 9(1.93,-0.25) 10(1.93,0.25) 11(1.93,0.751) 12(1.93,1.251) 19(-1.93,1.251) 20(-1.93,0.751) 21(-1.93,0.25) 22(-1.93,-0.25) 23(-1.93,-0.751) 24(-1.93,-1.251)
  rect 2.794x2.794 smd: PAD(0,0)
LSML126W90H59
  rect 0.889x2.54 smd: 1(-1.372,0) 2(1.372,0)
LSMSQ157H83
  rect 1.473x3.683 smd: 1(-1.232,0) 2(1.232,0)
QFN8_3X3_PAD2_44X1_7
  oval 0.305x0.914 smd: 1(-0.75,-1.557) 2(-0.25,-1.557) 3(0.25,-1.557) 4(0.75,-1.557) 5(0.75,1.557) 6(0.25,1.557) 7(-0.25,1.557) 8(-0.75,1.557)
  rect 2.438x1.702 smd: PAD(0,0)
QFN14_3_5X3_5_PAD2_05X2_05
  oval 0.889x0.305 smd: 1(-1.7,-0.75) 7(1.7,-0.75) 8(1.7,0.75) 14(-1.7,0.75)
  oval 0.305x0.889 smd: 2(-1,-1.7) 3(-0.5,-1.7) 4(0,-1.7) 5(0.5,-1.7) 6(1,-1.7) 9(1,1.7) 10(0.5,1.7) 11(0,1.7) 12(-0.5,1.7) 13(-1,1.7)
  rect 2.057x2.057 smd: PAD(0,0)
QFN24_4X4_2PAD
  oval 0.305x0.889 smd: 1(-1.25,-2.05) 2(-0.75,-2.05) 3(-0.25,-2.05) 4(0.25,-2.05) 5(0.75,-2.05) 6(1.25,-2.05) 13(1.25,2.05) 14(0.75,2.05) 15(0.25,2.05) 16(-0.25,2.05) 17(-0.75,2.05) 18(-1.25,2.05)
  oval 0.889x0.305 smd: 7(2.05,-1.25) 8(2.05,-0.75) 9(2.05,-0.25) 10(2.05,0.25) 11(2.05,0.75) 12(2.05,1.25) 19(-2.05,1.25) 20(-2.05,0.75) 21(-2.05,0.25) 22(-2.05,-0.25) 23(-2.05,-0.75) 24(-2.05,-1.25)
  rect 1.397x2.692 smd: PAD1(-0.648,0)
  rect 0.94x2.692 smd: PAD2(0.876,0)
R0402
  rect 0.889x0.813 smd: 1(-0.635,0) 2(0.635,0)
R0603
  rect 1.092x1.194 smd: 1(-0.851,0) 2(0.851,0)
R0805
  rect 1.295x1.397 smd: 1(-0.953,0) 2(0.953,0)
SC70
  rect 0.406x0.508 smd: 1(-0.65,-0.95) 2(0,-0.95) 3(0.65,-0.95) 4(0.65,0.95) 5(0,0.95) 6(-0.65,0.95)
SOT23
  rect 1.016x1.397 smd: 1(-0.94,-1.118) 2(0.94,-1.118) 3(0,1.118)
SOT363
  rect 0.33x0.889 smd: 1(-0.65,-1.118) 2(0,-1.118) 3(0.65,-1.118) 4(0.65,1.118) 5(0,1.118) 6(-0.65,1.118)
SOT-89
  rect 0.991x1.499 smd: 1(-1.5,-2.224) 3(1.5,-2.224)
  rect 0.991x1.981 smd: 2(0,-1.983)
  rect 2.007x2.997 smd: 4(0,0.728)
TSML63W31H29
  rect 0.254x0.559 smd: 1(-0.508,-0.394) 2(0,-0.394) 3(0.508,-0.394) 4(0.508,0.394) 5(0,0.394) 6(-0.508,0.394)
unnamed#2
  round 5.207 hole 3.937 unplated: (0,0)
US8
  rect 0.305x0.711 smd: 1(-0.75,-1.343) 2(-0.25,-1.343) 3(0.25,-1.343) 4(0.75,-1.343) 5(0.75,1.343) 6(0.25,1.343) 7(-0.25,1.343) 8(-0.75,1.343)

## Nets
5V5: C20.1(N1) C21.1(N1) C22.1(N1) C23.1(N1) C72.1(N1) C73.1(N1) C74.1(N1) C75.1(N1) C88.1(N1) C89.1(N1) C90.1(N1) L13.2(N2) P3.1(N1) R27.1(N1) U1.5(EN) U1.7(VIN2) U1.8(VIN1) U3.5(EN) U3.8(VIN) U12.5(EN) U12.7(VIN2) U12.8(VIN1) U13.5(EN) U13.8(VIN)
5V_3P3V_LNA1: C4.1(N1) C27.P(N1) C47.1(N1) C48.1(N1) C70.1(N1) L8.2(N2) LNA1.1(N1) R12.2(N2) U3.1(VOUT) U30.8(VCC)
5V_3P3V_LNA2: C10.1(N1) C11.1(N1) C78.P(N1) L3.2(N2) LNA2.1(N1) R20.2(N2) U13.1(VOUT)
5V_PREAMP1: AMP1.1(N1) C26.P(N1) C44.1(N1) C45.1(N1) C46.1(N1) C53.2(N2) C54.2(N2) C55.2(N2) C60.1(N1) C67.1(N1) C68.1(N1) C95.1(N1) C96.1(N1) C97.1(N1) C98.1(N1) C101.1(N1) C102.1(N1) L7.2(N2) R30.1(N1) U1.1(VOUT1) U1.2(VOUT2) U1.3(SENSE) U4.6(VCCB) U8.23(VCC1) U11.5(VDD) U15.5(VCC) U16.14(VCC)
5V_PREAMP2: AMP2.1(N1) C7.1(N1) C8.1(N1) C9.1(N1) C16.2(N2) C17.2(N2) C18.2(N2) C30.1(N1) C37.1(N1) C38.1(N1) C77.P(N1) L2.2(N2) R31.1(N1) U5.23(VCC1) U6.5(VDD) U12.1(VOUT1) U12.2(VOUT2) U12.3(SENSE)
AGND: C1.2(N2) C2.2(N2) C3.2(N2) C4.2(N2) C6.2(N2) C7.2(N2) C8.2(N2) C9.2(N2) C10.2(N2) C11.2(N2) C12.2(N2) C13.2(N2) C14.2(N2) C16.1(N1) C17.1(N1) C18.1(N1) C20.2(N2) C21.2(N2) C22.2(N2) C23.2(N2) C24.2(N2) C25.2(N2) C26.N(N2) C27.N(N2) C28.2(N2) C29.2(N2) C30.2(N2) C31.2(N2) C32.2(N2) C33.2(N2) C36.2(N2) C37.2(N2) C38.2(N2) C40.2(N2) C43.2(N2) C44.2(N2) C45.2(N2) C46.2(N2) C47.2(N2) C48.2(N2) C49.2(N2) C50.2(N2) C51.2(N2) C53.1(N1) C54.1(N1) C55.1(N1) C56.2(N2) C57.2(N2) C58.2(N2) C59.2(N2) C60.2(N2) C61.2(N2) C62.2(N2) C63.2(N2) C66.2(N2) C67.2(N2) C68.2(N2) C70.2(N2) C72.2(N2) C73.2(N2) C74.2(N2) C75.2(N2) C76.2(N2) C77.N(N2) C78.N(N2) C91.2(N2) C93.1(N1) C94.1(N1) C95.2(N2) C96.2(N2) C97.2(N2) C98.2(N2) C101.2(N2) C102.2(N2) D1.1(P) D1.2(N) D2.1(P) D2.2(N) DS1.C(N) FL1.1(GND1) FL1.3(GND2) FL2.1(GND1) FL2.3(GND2) FL3.1(GND1) FL3.3(GND2) FL4.1(GND1) FL4.3(GND2) P1.6(N6) P1.12(N12) P2.1(N1) P2.2(N2) P2.7(N7) P2.8(N8) P2.14(N14) P2.17(N17) P2.18(N18) P2.27(N27) P2.28(N28) P2.39(N39) P2.40(N40) P3.2(N2) R1.2(N2) R2.2(N2) R3.2(N2) R5.2(N2) R7.2(N2) R9.2(N2) R10.1(N1) R11.2(N2) R13.2(N2) R16.2(N2) R18.2(N2) R19.1(N1) R32.2(N2) RF_IO1.2(SH1) RF_IO1.3(SH2) RF_IO1.4(SH3) RF_IO1.5(SH4) RF_IO2.2(SH1) RF_IO2.3(SH2) RF_IO2.4(SH3) RF_IO2.5(SH4) RX1_A.2(SH1) RX1_A.3(SH2) RX2_A.2(SH1) RX2_A.3(SH2) T1.2(GROUND1) T1.5(GROUND2) T2.2(GROUND1) T2.5(GROUND2) TX1_A.2(SH1) TX1_A.3(SH2) TX1MON.2(SH1) TX1MON.3(SH2) TX2_A.2(SH1) TX2_A.3(SH2) TX2MON.2(SH1) TX2MON.3(SH2) U1.6(GND) U1.PAD(EP) U2.1(NC1) U2.2(NC2) U2.4(GND1) U2.5(NC3) U2.8(NC4) U2.9(GND2) U2.11(NC5) U2.12(NC6) U2.13(NC7) U2.15(NC8) U2.PAD U3.3(GND1) U3.6(GND2) U3.PAD U4.2(GND) U5.1(NC1) U5.2(NC2) U5.3(NC3) U5.5(GND) U5.6(NC4) U5.7(NC5) U5.8(NC6) U5.9(NC7) U5.10(NC8) U5.12(NC9) U5.13(NC10) U5.14(NC11) U5.18(NC12) U5.19(NC13) U5.21(NC14) U5.22(NC15) U5.24(NC16) U5.PAD U6.PAD U7.1(NC1) U7.2(NC2) U7.4(GND1) U7.5(NC3) U7.8(NC4) U7.9(GND2) U7.11(NC5) U7.12(NC6) U7.13(NC7) U7.15(NC8) U7.PAD U8.1(NC1) U8.2(NC2) U8.3(NC3) U8.5(GND) U8.6(NC4) U8.7(NC5) U8.8(NC6) U8.9(NC7) U8.10(NC8) U8.12(NC9) U8.13(NC10) U8.14(NC11) U8.18(NC12) U8.19(NC13) U8.21(NC14) U8.22(NC15) U8.24(NC16) U8.PAD U9.2(GND1) U9.4(GND2) U10.2(GND1) U10.4(GND2) U11.PAD U12.6(GND) U12.PAD(EP) U13.3(GND1) U13.6(GND2) U13.PAD U15.2(GND) U16.1(1OE_N) U16.4(2OE_N) U16.7(GND) U16.10(3OE_N) U16.13(4OE_N) U30.4(GND)
GND: C19.2(N2) C79.2(N2) C80.2(N2) C82.1(N1) C85.2(N2) C86.2(N2) C87.2(N2) C88.2(N2) C89.2(N2) C90.2(N2) R11.1(N1) R21.1(N1) R22.2(N2) R25.1(N1) R26.2(N2) R32.1(N1) U14.4(GND1) U14.8(PGND1) U14.9(PGND2) U14.10(PGND3) U14.11(PGND4) U14.12(PGND5) U14.13(PGND6) U14.PAD1(GND2)
AD9361_AUXADC: P1.5(N5) P2.19(N19)
AD9361_AUXDAC1: P1.7(N7) P2.21(N21)
AD9361_AUXDAC2: P1.8(N8) P2.23(N23)
AD9361_GPO0: P1.1(N1) P2.9(N9) U16.12(4A)
AD9361_GPO0_5V: U16.11(4Y) U30.5(A)
AD9361_GPO1: P1.2(N2) P2.11(N11) U16.9(3A)
AD9361_GPO1_5V: U16.8(3Y) U30.1(A)
AD9361_GPO2: P1.3(N3) P2.13(N13) U16.5(2A)
AD9361_GPO2_5V: U16.6(2Y) U30.2(B) U30.6(B)
AD9361_GPO3: P1.4(N4) P2.15(N15) U16.2(1A)
AD9361_GPO3_5V: R29.2(N2) U6.2(VCTL) U11.2(VCTL) U16.3(1Y)
RF_3V3: P2.10(N10) P2.12(N12) R15.1(N1)
RF_5V0: P2.3(N3) P2.4(N4) P2.5(N5) P2.6(N6)
RF_12V0: C92.1(N1) L1.1(N1) P2.37(N37) P2.38(N38)
RF_GPIO0: P1.9(N9) P2.31(N31) U4.3(A)
RF_GPIO0_5V: C57.1(N1) C58.1(N1) R4.1(N1) U15.6(Y1)
RF_GPIO1: P1.10(N10) P2.33(N33)
RF_GPIO1_5V: C25.1(N1) C28.1(N1) R8.1(N1) U15.4(Y2)
RF_GPIO2: P1.11(N11) P2.35(N35)
RF_GPIO_012_VDD: C93.2(N2) C94.2(N2) P2.29(N29) U4.1(VCCA) U4.5(DIR)
RX: C39.2(N2) C69.2(N2) L6.1(N1) L11.1(N1) U6.4(RX) U11.4(RX)
TX: C65.1(N1) T2.6(OUTPUT)
UNNAMED_2_ADHMC546_I144_ACG: C66.1(N1) U11.3(ACG)
UNNAMED_2_ADHMC546_I144_RFC: C71.1(N1) C91.1(N1) L10.2(N2) L11.2(N2) U11.6(RFC)
UNNAMED_2_ADHMC546_I144_TX: C65.2(N2) L10.1(N1) U11.1(TX)
UNNAMED_2_ADHMC669_I175_ACG: C3.1(N1) U7.6(ACG)
UNNAMED_2_ADHMC669_I175_RES: R2.1(N1) U7.7(RES)
UNNAMED_2_ADHMC669_I175_RFIN: C69.1(N1) U7.3(RFIN)
UNNAMED_2_ADHMC669_I175_RFOUT: D2.3(C) FL2.4(IN) U7.10(RFOUT)
UNNAMED_2_ADHMC669_I175_VCTL: C51.1(N1) U7.16(VCTL) U30.3(Y)
UNNAMED_2_ADHMC669_I175_VDD: L8.1(N1) U7.14(VDD)
UNNAMED_2_ADHMC921_I79_RFIN: C52.2(N2) U8.4(RFIN)
UNNAMED_2_ADHMC921_I79_RFOUT: C59.1(N1) C63.1(N1) C64.1(N1) L9.1(N1) U8.15(RFOUT/VCC2_1) U8.16(RFOUT/VCC2_2) U8.17(RFOUT/VCC2_3)
UNNAMED_2_ADHMC921_I79_VEN: R4.2(N2) U8.20(VEN)
UNNAMED_2_ADL5324_I116_RFIN: C42.2(N2) C43.1(N1) U10.1(RFIN)
UNNAMED_2_ADL5324_I116_RFOUT: C49.1(N1) C50.1(N1) C52.1(N1) L7.1(N1) U10.3(RFOUT)
UNNAMED_2_CAP_I54_N1: C61.1(N1) C62.1(N1) L9.2(N2) R30.2(N2)
UNNAMED_2_CAP_I99_N1: C42.1(N1) FL1.2(OUT)
UNNAMED_2_CAP_I148_N2: C71.2(N2) RF_IO1.1(CNTR)
UNNAMED_2_CAP_I196_N2: C64.2(N2) T2.1(INPUT)
UNNAMED_2_CNBNC3P_I83_CNTR: FL1.4(IN) TX1_A.1(CNTR)
UNNAMED_2_CNBNC3P_I86_CNTR: R13.1(N1) R14.1(N1) TX1MON.1(CNTR)
UNNAMED_2_CNBNC3P_I158_CNTR: FL2.2(OUT) RX1_A.1(CNTR)
UNNAMED_2_RES_I197_N1: R18.1(N1) T2.4(TERMINATION)
UNNAMED_2_RES_I198_N2: R14.2(N2) R16.1(N1) T2.3(COUPLED)
UNNAMED_3_ADHMC546_I36_ACG: C36.1(N1) U6.3(ACG)
UNNAMED_3_ADHMC546_I36_RFC: C40.1(N1) C41.1(N1) L5.2(N2) L6.2(N2) U6.6(RFC)
UNNAMED_3_ADHMC546_I36_TX: C35.2(N2) L5.1(N1) U6.1(TX)
UNNAMED_3_ADHMC669_I19_ACG: C1.1(N1) U2.6(ACG)
UNNAMED_3_ADHMC669_I19_RES: R1.1(N1) U2.7(RES)
UNNAMED_3_ADHMC669_I19_RFIN: C39.1(N1) U2.3(RFIN)
UNNAMED_3_ADHMC669_I19_RFOUT: D1.3(C) FL4.4(IN) U2.10(RFOUT)
UNNAMED_3_ADHMC669_I19_VCTL: C14.1(N1) U2.16(VCTL) U30.7(Y)
UNNAMED_3_ADHMC669_I19_VDD: L3.1(N1) U2.14(VDD)
UNNAMED_3_ADHMC921_I94_RFIN: C15.2(N2) U5.4(RFIN)
UNNAMED_3_ADHMC921_I94_RFOUT: C29.1(N1) C33.1(N1) C34.1(N1) L4.1(N1) U5.15(RFOUT/VCC2_1) U5.16(RFOUT/VCC2_2) U5.17(RFOUT/VCC2_3)
UNNAMED_3_ADHMC921_I94_VEN: R8.2(N2) U5.20(VEN)
UNNAMED_3_ADL5324_I56_RFIN: C5.2(N2) C6.1(N1) U9.1(RFIN)
UNNAMED_3_ADL5324_I56_RFOUT: C12.1(N1) C13.1(N1) C15.1(N1) L2.1(N1) U9.3(RFOUT)
UNNAMED_3_CAP_I35_N1: C35.1(N1) T1.6(OUTPUT)
UNNAMED_3_CAP_I45_N2: C41.2(N2) RF_IO2.1(CNTR)
UNNAMED_3_CAP_I53_N1: C5.1(N1) FL3.2(OUT)
UNNAMED_3_CAP_I91_N1: C31.1(N1) C32.1(N1) L4.2(N2) R31.2(N2)
UNNAMED_3_CAP_I127_N2: C34.2(N2) T1.1(INPUT)
UNNAMED_3_CNBNC3P_I21_CNTR: R5.1(N1) R6.1(N1) TX2MON.1(CNTR)
UNNAMED_3_CNBNC3P_I51_CNTR: FL3.4(IN) TX2_A.1(CNTR)
UNNAMED_3_CNBNC3P_I105_CNTR: FL4.2(OUT) RX2_A.1(CNTR)
UNNAMED_3_RES_I126_N1: R9.1(N1) T1.4(TERMINATION)
UNNAMED_3_RES_I129_N1: R6.2(N2) R7.1(N1) T1.3(COUPLED)
UNNAMED_5_7445V2_I198_B: R28.1(N1) U4.4(B)
UNNAMED_5_ADM7171_I71_SS: C2.1(N1) U1.4(SS)
UNNAMED_5_ADM7171_I103_SS: C76.1(N1) U12.4(SS)
UNNAMED_5_ADP238X_I108_BST: C81.1(N1) U14.15(BST)
UNNAMED_5_ADP238X_I108_COMP: C84.1(N1) C86.1(N1) U14.1(COMP)
UNNAMED_5_ADP238X_I108_EN: R21.2(N2) R23.2(N2) U14.20(EN)
UNNAMED_5_ADP238X_I108_FB: R24.1(N1) R25.2(N2) U14.2(FB)
UNNAMED_5_ADP238X_I108_PVIN1: C19.1(N1) C79.1(N1) L1.2(N2) R23.1(N1) U14.16(PVIN1) U14.17(PVIN2) U14.18(PVIN3) U14.19(PVIN4)
UNNAMED_5_ADP238X_I108_RT: R22.1(N1) U14.22(RT)
UNNAMED_5_ADP238X_I108_SS: C80.1(N1) U14.24(SS)
UNNAMED_5_ADP238X_I108_SW1: C81.2(N2) L12.1(N1) U14.5(SW1) U14.6(SW2) U14.7(SW3) U14.14(SW4) U14.PAD2(SW5)
UNNAMED_5_ADP238X_I108_VREG: C82.2(N2) U14.3(VREG)
UNNAMED_5_ADP7104_I52_SENSE: R10.2(N2) R12.1(N1) U3.2(SENSE)
UNNAMED_5_ADP7104_I92_SENSE: R19.2(N2) R20.1(N1) U13.2(SENSE)
UNNAMED_5_CAP_I117_N1: C83.1(N1) C85.1(N1) C87.1(N1) L12.2(N2) L13.1(N1)
UNNAMED_5_CAP_I117_N2: C83.2(N2) R24.2(N2) R27.2(N2)
UNNAMED_5_CAP_I127_N2: C84.2(N2) R26.1(N1)
UNNAMED_5_CAP_I146_N2: C92.2(N2) R3.1(N1)
UNNAMED_5_DIOLED_I85_P: DS1.A(P) R15.2(N2)
UNNAMED_5_NC7WZ17P6X_I161_A1: R28.2(N2) R29.1(N1) U15.1(A1) U15.3(A2)
VDET_HMC921_1: C56.1(N1) P2.25(N25) U8.11(VDET)
VDET_HMC921_2: C24.1(N1) P2.26(N26) U5.11(VDET)

Pads without a net: P2 16 20 22 24 30 32 34 36; U3 4 7; U13 4 7; U14 21 23; U16 PAD

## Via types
v1: diameter 0.406, hole 0.203, L3_PWR to BOTTOM, 157 vias
v2: diameter 0.406, hole 0.203, TOP to BOTTOM, 733 vias
v3: diameter 0.406, hole 0.203, TOP to L2_GND, 2575 vias
v4: diameter 0.508, hole 0.203, TOP to BOTTOM, 80 vias

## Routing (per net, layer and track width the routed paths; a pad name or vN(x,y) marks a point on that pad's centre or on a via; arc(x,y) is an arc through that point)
5V5: length 14.7
  BOTTOM w0.305: U3.5 86.9,41.39 87.46,41.94 90.87,41.94 ; U13.5 86.76,12.18 87.44,12.86 90.74,12.86 ; U1.5 87.18,53.96 87.19,53.97 88.44,53.97 ; C72.1 87.44,27.56 87.43,27.54 U12.5
5V_3P3V_LNA1: length 1.1
  BOTTOM w0.305: 57.28,36.38 U30.8 57.94,36.84
  vias: v1(57.09,36.1) v1(58.1,36.1) v1(58.86,35.85) v1(59.75,35.85) v1(60.64,35.85) v1(61.53,35.85) v1(62.17,37.12) v1(62.17,36.36) v1(80.71,38.9) v1(82.1,39.4) v1(82.49,38.9) v1(83.25,38.9) v1(83.25,38.01) v1(83.25,37.24) v2(75.37,35.72) v2(75.94,36.74) v2(75.94,36.23) v2(75.94,35.72) v2(75.94,35.09) v2(76.01,34.32)
5V_3P3V_LNA2:
  vias: v1(79.95,9.69) v1(80.76,9.66) v1(81.47,9.63) v1(82.23,9.69) v1(82.99,9.69) v1(82.99,8.8) v1(82.99,7.91) v2(74.74,6.79) v2(75.37,6.79) v2(75.98,7.04) v2(75.98,6.41) v2(76.01,5.77) v2(76.01,5.14)
5V_PREAMP1: length 10.9
  TOP w0.254: U8.23 67.25,53.15 65.97,54.43 65.97,54.63
  TOP w0.305: U11.5 v2(87.77,45.82)
  BOTTOM w0.406: C98.1 69.28,36.7 U15.5 ; C102.1 52.72,46.26 51.97,47.01 U16.14
  BOTTOM w0.508: v1(69.53,39.43) 69.82,39.14 C97.1 C98.1
  vias: v1(56.83,46.52) v1(56.83,45.88) v1(65.07,43.89) v1(65.07,43.25) v1(65.07,42.49) v1(65.07,41.86) v1(65.07,41.22) v1(65.81,40.59) v1(66.34,40.59) v1(78.93,50.83) v1(79.56,50.83) v1(80.2,50.83) v1(80.83,50.83) v1(81.47,50.83) v1(82.1,53.37) v1(82.1,52.74) v1(82.1,52.1) v1(82.1,51.47) v1(82.1,50.83) v2(40.7,57.44) v2(40.7,56.8) v2(40.7,56.17) v2(41.21,55.53) v2(41.46,56.04) v2(41.72,54.14) v2(42.1,56.04) v2(42.35,54.14) v2(42.73,56.04) v2(66.36,58.71) v2(66.36,58.2) v2(66.36,57.69) v2(66.36,56.42) v2(66.36,55.91) v2(74.74,57.82) v2(74.74,57.31) v2(74.74,56.8) v2(74.74,56.29) v2(86.55,42.32) v2(87.12,42.32) v2(87.63,43.59) v2(87.63,42.83)
5V_PREAMP2: length 3.5
  TOP w0.254: U5.23 67.25,24.78 65.96,26.07 65.96,26.28
  TOP w0.305: U6.5 v2(87.79,20.67)
  vias: v1(79.06,24.54) v1(79.69,24.54) v1(80.33,24.54) v1(80.96,24.54) v1(81.6,24.54) v1(82.23,27.08) v1(82.23,26.45) v1(82.23,25.81) v1(82.23,25.18) v1(82.23,24.54) v2(41.34,25.43) v2(41.34,24.04) v2(41.59,27.72) v2(41.97,25.43) v2(41.97,24.04) v2(42.48,27.72) v2(43.37,27.72) v2(66.35,28.06) v2(66.35,27.56) v2(66.47,30.22) v2(66.47,29.72) v2(66.47,29.21) v2(74.73,29.46) v2(74.73,28.95) v2(74.73,28.45) v2(74.73,27.94) v2(86.8,17.18) v2(87.82,18.45) v2(87.82,17.18) v2(87.82,15.78)
AGND: length 111.3
  TOP w0.203: 80.48,37.52 80.41,37.59 U7.2
  TOP w0.254: v3(79.06,35.72) 78.89,35.89 U7.15 ; U2.13 v3(77.46,7.35) ; v3(76.77,7.68) 77.13,8.04 U2.12 ; 80.48,37.52 81.09,37.52 v3(81.22,37.4) ; 81.47,8.26 81.27,8.47 80.17,8.47 U2.2 ; U7.12 77.15,37.09 76.9,36.84 v3(76.9,36.69) ; U7.13 v3(77.41,36.41) ; U7.1 80.45,37.09 v3(80.76,36.79) ; v3(76.36,8.36) 76.47,8.47 77.16,8.47 U2.11 ; U2.1 80.73,8.04 80.83,7.93 v3(80.96,7.93)
  TOP w0.305: DS1.C v2(2.72,32.88)
  TOP w0.508: 23.39,57.27 P3.2 ; P3.2 25,58.88 ; P3.2 25,57.27 ; P3.2 23.39,58.88 ; C14.2 v3(81.34,6.79) ; 47.22,32.08 P1.12 ; P1.12 48.92,32.08 ; P1.12 48.92,33.78 ; P1.12 47.22,33.78 ; C51.2 v3(81.47,35.72) ; 39.6,32.08 P1.6 ; P1.6 39.6,33.78 ; P1.6 41.3,33.78 ; P1.6 41.3,32.08
  L3_PWR w0.508: P1.12 49.01,31.99 ; P1.12 47.13,33.87 ; P1.12 47.13,31.99 ; P1.12 49.01,33.87
  BOTTOM w0.254: U16.4 v2(48.7,43.34)
  BOTTOM w0.305: v2(80.45,30.64) 80.44,30.63 C77.N ; U1.6 84.88,53.46 v4(84.63,53.21) ; v2(68.77,38.9) 68.59,39.07 U4.2 ; U16.10 48.2,48.73 v2(48.07,48.86) ; U16.1 50.4,45.97 ; U16.1 50.4,45.05 ; U16.1 51.15,45.51 ; 55.25,38.34 U30.4 54.59,38.8 ; 87.18,40.67 86.97,40.89 U3.6 84.88,40.89 U3.PAD 84.38,40.89 U3.3 82.53,40.89 82.23,41.18 82.23,41.94 ; 47,45.05 U16.7 ; U16.7 46.25,45.51 ; U16.7 47,45.97 ; C76.2 85.5,29.59 v2(85.53,29.62) ; v2(87.18,30.39) 87.22,30.35 C72.2 ; v2(87.06,11.59) 86.97,11.68 U13.6 84.88,11.68 v4(84.63,11.43) 84.38,11.68 U13.3 82.53,11.68 82.23,11.97 82.23,12.73 ; v4(84.63,26.79) 84.88,27.04 U12.6 v2(86.84,27.04)
  BOTTOM w0.508: 49.01,33.87 P1.12 47.13,33.87 ; v2(15.05,30.89) 14.96,30.81 P2.14 ; C95.2 v2(68.77,43.64) ; v2(68.77,42.58) 68.98,42.37 C94.1 ; v2(20.64,30.89) 20.56,30.82 P2.28 ; P2.17 v2(16.56,32.29) ; v2(20.89,39.53) 20.76,39.4 R3.2 ; P1.6 41.39,33.87 ; P1.6 41.39,31.99 ; P1.6 39.51,31.99 ; P1.6 39.51,33.87 ; P2.7 12.56,32.47 v2(12.38,32.29) ; v2(68.77,41.82) 68.57,41.61 C96.2 ; C98.2 72.33,37.24 v2(72.45,37.37) ; v2(84.56,36.19) 84.64,36.1 ; v2(72.71,42.32) 72.66,42.37 C93.1 ; v2(90.61,40.17) 89.47,40.17 88.96,40.67 89.47,41.18 v2(90.61,41.18) ; P2.27 v2(20.56,32.29) ; C93.1 C94.1 ; C93.1 v2(71.7,43.33) ; C94.1 v2(69.92,43.34) ; v2(13.02,31.02) 12.56,30.57 P2.8 ; P2.1 v2(10.16,32.29) ; P2.39 v2(25.36,32.29) ; v2(87.06,11.59) C73.2 90.11,11.59 v2(90.23,11.46) ; P2.40 v2(25.36,30.77) ; C97.2 72.33,39.02 v2(72.45,38.9) ; P2.2 v2(10.16,30.89)
  BOTTOM w0.762: 84.56,35.76 v2(84.56,36.19) C23.2 84.56,40.56 U3.PAD ; v4(84.63,11.43) 84.43,11.22 C75.2 84.43,6.55 v2(82.99,5.11)
  vias: v1(88.33,12.1) v1(88.33,11.21) v1(89.22,12.1) v1(89.22,11.21) v2(0.95,31.91) v2(0.95,30.89) v2(1.21,31.4) v2(1.46,31.91) v2(1.46,30.89) v2(1.71,31.4) v2(1.97,31.91) v2(1.97,30.89) v2(2.09,34.45) v2(2.09,28.1) v2(2.35,39.53) v2(2.35,38.9) v2(2.6,38.13) v2(2.73,9.05) v2(3.24,38.13) v2(3.62,31.4) v2(3.87,38.13) v2(3.87,31.91) v2(3.87,30.89) v2(4,36.99) v2(4,25.56) v2(4.13,31.4) v2(4.38,31.91) v2(4.38,30.89) v2(4.51,38.13) v2(4.63,31.4) v2(4.76,39.53) v2(4.76,38.9) v2(4.89,31.91) v2(4.89,30.89) v2(5.14,38.13) v2(5.14,31.4) v2(5.4,31.91) v2(5.4,30.89) v2(5.65,31.4) v2(5.78,38.13) v2(5.9,34.45) v2(5.9,31.91) v2(5.9,30.89) v2(6.16,31.4) v2(6.41,38.13) v2(7.81,26.83) v2(7.81,24.29) v2(7.81,10.32) v2(7.81,6.51) v2(7.81,2.7) v2(9.21,31.53) v2(9.46,32.04) v2(9.46,31.02) v2(9.71,31.53) v2(11.62,26.83) v2(11.62,15.4) v2(11.62,6.51) v2(11.62,2.7) v2(12.64,39.53) v2(12.76,31.53) v2(13.02,32.04) v2(13.27,31.53) v2(13.52,32.04) v2(13.52,31.02) v2(13.52,19.85) v2(13.78,31.53) v2(14.03,32.04) v2(14.03,31.02) v2(14.29,31.53) v2(14.54,32.04) v2(14.54,31.02) v2(14.79,31.53) v2(15.05,32.04) v2(15.3,31.53) v2(15.43,24.29) v2(15.43,15.4) v2(15.43,6.51) v2(15.43,2.7) v2(15.56,32.04) v2(15.81,31.53) v2(16.06,32.04) v2(16.32,31.53) v2(16.57,31.02) v2(16.7,11.59) v2(16.83,31.53) v2(17.08,32.04) v2(17.08,31.02) v2(17.33,31.53) v2(17.33,19.85) v2(17.59,32.04) v2(17.59,31.02) v2(17.84,31.53) v2(18.1,32.04) v2(18.1,31.02) v2(18.35,31.53) v2(18.6,32.04) v2(18.6,31.02) v2(18.86,31.53) v2(19.11,32.04) v2(19.11,31.02) v2(19.24,24.29) v2(19.24,15.4) v2(19.24,6.51) v2(19.24,2.7) v2(19.37,31.53) v2(19.62,32.04) v2(19.62,31.02) v2(19.87,31.53) v2(20.13,32.04) v2(20.13,31.02) v2(20.38,31.53) v2(20.51,11.59) v2(20.89,31.53) v2(21.14,32.04) v2(21.14,31.02) v2(21.14,19.85) v2(21.4,31.53) v2(21.65,32.04) v2(21.65,31.02) v2(21.91,31.53) v2(22.16,32.04) v2(22.16,31.02) v2(22.41,31.53) v2(22.67,32.04) v2(22.67,31.02) v2(22.92,31.53) v2(23.05,15.4) v2(23.05,6.51) v2(23.05,2.7) v2(23.18,32.04) v2(23.18,31.02) v2(23.43,31.53) v2(23.68,32.04) v2(23.68,31.02) v2(23.94,31.53) v2(24.32,24.29) v2(24.32,11.59) v2(24.95,19.85) v2(25.46,31.53) v2(25.97,31.53) v2(26.22,32.04) v2(26.22,31.02) v2(26.86,28.1) v2(26.86,24.29) v2(26.86,15.4) v2(26.86,6.51) v2(26.86,2.7) v2(28.13,11.59) v2(29.27,31.53) v2(29.53,32.04) v2(29.53,31.02) v2(29.78,31.53) v2(30.67,24.29) v2(30.67,15.4) v2(30.67,6.51) v2(30.67,2.7) v2(31.94,11.59) v2(34.48,24.29) v2(34.48,15.4) v2(34.48,6.51) v2(34.48,2.7) v2(34.61,36.36) v2(35.75,11.59) v2(38.29,47.15) v2(38.29,15.4) v2(38.29,6.51) v2(38.29,2.7) v2(38.67,42.07) v2(39.56,11.59) v2(40.19,35.72) v2(40.83,47.15) v2(41.46,42.71) v2(42.1,48.42) v2(42.1,15.4) v2(42.1,6.51) v2(42.1,2.7) v2(43.37,35.72) v2(43.37,11.59) v2(43.88,24.67) v2(43.88,24.04) v2(44.77,54.64) v2(45.15,56.17) v2(45.91,48.42) v2(45.91,35.72) v2(45.91,15.4) v2(45.91,2.7) v2(46.16,57.44) v2(46.48,46.39) v2(47.05,46.39) v2(47.18,11.59) v2(48.07,25.81) v2(49.59,26.45) v2(49.72,35.72) v2(49.72,15.4) v2(50.1,32.16) v2(50.1,31.15) v2(50.23,48.23) v2(50.23,47.66) v2(50.35,31.66) v2(50.61,32.16) v2(50.61,31.15) v2(50.67,46.32) v2(50.86,42.71) v2(50.86,31.66) v2(50.99,29.37) v2(50.99,24.29) v2(50.99,11.59) v2(51.12,32.16) v2(51.12,31.15) v2(51.31,46.32) v2(51.37,31.66) v2(51.62,45.88) v2(51.62,32.16) v2(51.62,31.15) v2(51.88,31.66) v2(52.13,32.16) v2(52.13,31.15) v2(52.26,26.83) v2(52.39,31.66) v2(52.64,32.16) v2(52.64,31.15) v2(52.89,31.66) v2(53.15,32.16) v2(53.15,31.15) v2(53.4,31.66) v2(53.53,42.71) v2(53.66,32.16) v2(53.66,31.15) v2(53.91,31.66) v2(54.16,32.16) v2(54.16,31.15) v2(54.42,31.66) v2(54.55,48.67) v2(54.55,48.04) v2(54.55,39.53) v2(54.67,32.16) v2(54.67,31.15) v2(54.8,29.37) v2(54.8,24.29) v2(54.8,11.59) v2(54.8,6.51) v2(54.93,31.66) v2(55.18,32.16) v2(55.18,31.15) v2(55.43,52.23) v2(55.43,31.66) v2(55.69,32.16) v2(55.69,31.15) v2(56.07,42.71) v2(56.58,48.67) v2(56.58,48.04) v2(56.7,53.5) v2(56.83,32.16) v2(56.83,31.15) v2(57.09,31.66) v2(57.34,32.16) v2(57.34,31.15) v2(57.34,29.37) v2(57.34,24.29) v2(57.59,31.66) v2(57.72,20.48) v2(57.85,32.16) v2(57.85,31.15) v2(57.97,54.77) v2(57.97,52.23) v2(58.1,31.66) v2(58.36,32.16) v2(58.36,31.15) v2(58.61,31.66) v2(58.61,6.51) v2(58.86,39.4) v2(58.86,32.16) v2(58.86,31.15) v2(59.12,31.66) v2(59.24,56.04) v2(59.24,53.5) v2(59.43,39.4) v2(59.37,32.16) v2(59.37,31.15) v2(59.63,31.66) v2(59.88,42.71) v2(59.88,32.16) v2(59.88,31.15) v2(59.88,29.37) v2(59.88,26.83) v2(59.88,11.59) v2(60.13,31.66) v2(60.39,32.16) v2(60.39,31.15) v2(60.51,57.31) v2(60.51,54.77) v2(60.51,52.23) v2(60.64,31.66) v2(60.77,20.48) v2(60.9,39.4) v2(60.9,32.16) v2(60.9,31.15) v2(61.15,31.66) v2(61.15,24.29) v2(61.4,32.16) v2(61.4,31.15) v2(61.47,39.4) v2(61.66,31.66) v2(61.78,42.71) v2(61.91,32.16) v2(61.91,31.15) v2(61.91,28.1) v2(62.17,31.66) v2(62.36,56.74) v2(62.42,55.79) v2(62.42,32.16) v2(62.42,31.15) v2(62.42,15.4) v2(62.42,6.51) v2(62.55,28.1) v2(62.67,31.66) v2(62.93,32.16) v2(62.93,31.15) v2(62.99,56.74) v2(63.05,55.79) v2(63.18,31.66) v2(63.31,27.59) v2(63.31,25.94) v2(63.44,32.16) v2(63.44,31.15) v2(63.56,55.02) v2(63.56,53.5) v2(63.69,42.71) v2(63.69,31.66) v2(63.69,11.59) v2(63.94,32.16) v2(63.94,31.15) v2(64.07,20.1) v2(64.2,55.02) v2(64.2,53.5) v2(64.2,31.66) v2(64.45,32.16) v2(64.45,31.15) v2(64.71,31.66) v2(64.96,32.16) v2(64.96,31.15) v2(64.96,15.4) v2(65.21,31.66) v2(65.47,32.16) v2(65.47,31.15) v2(65.72,31.66) v2(65.98,32.16) v2(65.98,31.15) v2(66.23,31.66) v2(66.23,6.51) v2(66.48,32.16) v2(66.48,31.15) v2(66.74,31.66) v2(66.99,32.16) v2(66.99,31.15) v2(67.12,46.52) v2(67.25,31.66) v2(67.5,32.16) v2(67.5,31.15) v2(67.5,11.59) v2(67.75,31.66) v2(67.94,35.91) v2(68.01,32.16) v2(68.01,31.15) v2(68.2,36.8) v2(68.26,31.66) v2(68.52,32.16) v2(68.52,31.15) v2(68.77,15.4) v2(69.79,56.29) v2(69.79,27.97) v2(70.04,32.16) v2(70.04,31.15) v2(70.04,6.51) v2(70.29,56.29) v2(70.29,31.66) v2(70.29,27.97) v2(70.55,32.16) v2(70.55,31.15) v2(70.8,31.66) v2(71.06,32.16) v2(71.06,31.15) v2(71.31,31.66) v2(71.31,11.59) v2(71.56,32.16) v2(71.56,31.15) v2(71.82,31.66) v2(72.07,32.16) v2(72.07,31.15) v2(72.33,31.66) v2(72.33,7.65) v2(72.33,5.75) v2(72.45,36.74) v2(72.45,34.83) v2(72.58,32.16) v2(72.58,31.15) v2(72.58,15.4) v2(72.83,31.66) v2(72.96,52.87) v2(72.96,49.18) v2(72.96,47.4) v2(72.96,24.67) v2(72.96,24.04) v2(72.96,6.76) v2(72.96,4.73) v2(73.09,32.16) v2(73.09,31.15) v2(73.09,20.86) v2(73.09,19.59) v2(73.21,52.23) v2(73.34,31.66) v2(73.6,52.87) v2(73.6,32.16) v2(73.6,31.15) v2(73.6,24.67) v2(73.85,31.66) v2(73.98,54.64) v2(73.97,26.41) v2(74.1,32.16) v2(74.1,31.15) v2(74.1,11.97) v2(74.36,31.66) v2(74.61,32.16) v2(74.61,31.15) v2(74.74,12.61) v2(74.74,11.97) v2(75.5,42.32) v2(75.5,40.04) v2(76.14,55.28) v2(76.14,32.16) v2(76.14,31.15) v2(76.26,27.08) v2(76.39,31.66) v2(76.39,16.67) v2(76.64,32.16) v2(76.64,31.15) v2(76.9,55.28) v2(76.9,31.66) v2(76.9,27.08) v2(77.15,32.16) v2(77.15,31.15) v2(77.41,31.66) v2(77.53,27.08) v2(77.66,32.16) v2(77.66,31.15) v2(77.91,31.66) v2(78.17,55.53) v2(78.17,32.16) v2(78.17,31.15) v2(78.17,30.13) v2(78.42,31.66) v2(78.68,32.16) v2(78.68,31.15) v2(78.8,55.53) v2(78.8,30.13) v2(78.93,31.66) v2(78.93,15.4) v2(79.18,32.16) v2(79.18,31.15) v2(79.44,31.66) v2(79.69,32.16) v2(79.69,31.15) v2(79.95,31.66) v2(80.07,56.93) v2(80.2,32.16) v2(80.2,31.15) v2(80.45,31.66) v2(80.71,56.93) v2(80.71,32.16) v2(80.71,31.15) v2(80.71,3.59) v2(80.96,31.66) v2(81.22,32.16) v2(81.22,31.15) v2(81.34,56.93) v2(81.34,3.59) v2(81.47,31.66) v2(81.72,32.16) v2(81.72,31.15) v2(81.85,54.9) v2(81.98,31.66) v2(81.98,29.62) v2(81.98,28.99) v2(81.98,28.35) v2(81.98,3.59) v2(82.23,32.16) v2(82.23,31.15) v2(82.42,15.46) v2(82.49,31.66) v2(82.61,3.59) v2(82.74,32.16) v2(82.74,31.15) v2(82.74,16.67) v2(82.99,31.66) v2(82.99,5.75) v2(82.99,4.48) v2(83.06,42.58) v2(83.25,32.16) v2(83.25,31.15) v2(83.18,15.46) v2(83.5,31.66) v2(83.82,42.58) v2(83.76,32.16) v2(83.76,31.15) v2(84.01,34.45) v2(84.01,31.66) v2(84.26,32.16) v2(84.26,31.15) v2(84.26,18.32) v2(84.26,16.42) v2(84.39,57.06) v2(84.52,31.66) v2(84.77,32.16) v2(84.77,31.15) v2(85.03,57.06) v2(85.03,31.66) v2(85.28,32.16) v2(85.28,31.15) v2(85.28,6.51) v2(85.28,2.7) v2(85.41,56.04) v2(85.53,31.66) v2(85.79,32.16) v2(85.79,31.15) v2(86.17,32.67) v2(86.17,31.66) v2(86.42,32.16) v2(86.68,32.67) v2(86.68,31.66) v2(86.93,32.16) v2(87.06,57.06) v2(87.06,56.29) v2(87.18,40.04) v2(87.18,32.67) v2(87.18,31.66) v2(87.44,49.69) v2(87.44,49.06) v2(87.44,32.16) v2(87.69,32.67) v2(87.69,31.66) v2(87.69,23.66) v2(87.82,40.04) v2(87.82,34.45) v2(87.95,32.16) v2(88.2,32.67) v2(88.2,31.66) v2(88.45,32.16) v2(88.71,32.67) v2(88.71,31.66) v2(88.96,32.16) v2(89.09,6.51) v2(89.09,2.7) v2(89.22,32.67) v2(89.22,31.66) v2(89.85,49.69) v2(89.85,49.06) v2(89.85,48.29) v2(92.9,6.51) v2(92.9,2.7) v2(93.79,32.67) v2(93.79,31.66) v2(94.04,32.16) v2(94.3,32.67) v2(94.3,31.66) v2(94.42,52.74) v2(94.42,51.98) v2(94.42,51.21) v2(94.42,50.45) v2(94.42,49.69) v2(94.42,43.34) v2(94.42,42.58) v2(94.42,41.82) v2(94.42,41.05) v2(94.42,40.29) v2(94.42,27.59) v2(94.42,26.83) v2(94.42,26.07) v2(94.42,25.31) v2(94.42,24.54) v2(94.42,18.07) v2(94.42,17.31) v2(94.42,16.54) v2(94.42,15.78) v2(94.42,15.02) v2(94.55,32.16) v2(94.8,32.67) v2(94.8,31.66) v2(95.06,32.16) v2(95.19,52.74) v2(95.19,40.29) v2(95.19,27.59) v2(95.19,15.02) v2(95.31,32.67) v2(95.31,31.66) v2(95.44,11.59) v2(95.44,7.78) v2(95.57,32.16) v2(95.82,32.67) v2(95.82,31.66) v2(95.95,52.74) v2(95.95,40.29) v2(95.95,27.59) v2(95.95,15.02) v2(96.07,32.16) v2(96.33,32.67) v2(96.33,31.66) v2(96.58,32.16) v2(96.71,52.74) v2(96.71,40.29) v2(96.71,27.59) v2(96.71,15.02) v2(96.84,32.67) v2(96.84,31.66) v2(97.09,32.16) v2(97.34,32.67) v2(97.34,31.66) v2(97.47,52.74) v2(97.47,40.29) v2(97.47,27.59) v2(97.47,15.02) v2(97.6,32.16) v2(97.85,32.67) v2(97.85,31.66) v2(98.11,32.16) v2(98.23,52.74) v2(98.23,40.29) v2(98.23,27.59) v2(98.23,15.02) v2(98.36,32.67) v2(98.36,31.66) v2(98.61,32.16) v2(98.87,32.67) v2(98.87,31.66) v2(99,52.74) v2(99,40.29) v2(99,27.59) v2(99,15.02) v3(1.97,44.86) v3(1.97,43.98) v3(1.97,43.34) v3(1.97,42.71) v3(1.97,42.07) v3(1.97,41.44) v3(1.97,40.8) v3(1.97,40.04) v3(1.97,24.16) v3(1.97,23.27) v3(1.97,22.64) v3(1.97,22) v3(1.97,21.37) v3(1.97,20.73) v3(1.97,20.1) v3(1.97,19.34) v3(1.97,15.4) v3(1.97,14.51) v3(1.97,13.88) v3(1.97,13.24) v3(1.97,12.61) v3(1.97,11.97) v3(1.97,11.34) v3(1.97,10.57) v3(2.6,44.86) v3(2.6,40.04) v3(2.6,24.16) v3(2.6,19.34) v3(2.6,15.4) v3(2.6,10.57) v3(3.24,44.86) v3(3.24,40.04) v3(3.24,24.16) v3(3.24,19.34) v3(3.24,15.4) v3(3.24,10.57) v3(3.87,44.86) v3(3.87,40.04) v3(3.87,24.16) v3(3.87,19.34) v3(3.87,15.4) v3(3.87,10.57) v3(4.51,44.86) v3(4.51,40.04) v3(4.51,24.16) v3(4.51,19.34) v3(4.51,15.4) v3(4.51,10.57) v3(5.14,44.86) v3(5.14,44.23) v3(5.14,43.59) v3(5.14,41.31) v3(5.14,40.67) v3(5.14,40.04) v3(5.14,24.16) v3(5.14,23.53) v3(5.14,22.89) v3(5.14,20.61) v3(5.14,19.97) v3(5.14,19.34) v3(5.14,15.4) v3(5.14,14.77) v3(5.14,14.13) v3(5.14,11.84) v3(5.14,11.21) v3(5.14,10.57) v3(5.78,22.89) v3(5.78,20.61) v3(5.78,14.13) v3(5.78,11.84) v3(6.16,43.59) v3(6.16,41.31) v3(6.16,13.75) v3(6.16,12.23) v3(6.41,22.64) v3(6.41,21.12) v3(6.41,14.26) v3(6.67,43.21) v3(6.67,41.69) v3(6.79,13.75) v3(6.79,12.23) v3(6.92,19.85) v3(6.92,18.96) v3(6.92,18.32) v3(6.92,17.69) v3(6.92,17.05) v3(6.92,16.42) v3(6.92,15.78) v3(6.92,15.02) v3(7.05,49.31) v3(7.05,48.42) v3(7.05,47.79) v3(7.05,47.15) v3(7.05,46.52) v3(7.05,45.88) v3(7.05,45.25) v3(7.05,44.48) v3(7.05,40.55) v3(7.05,39.66) v3(7.05,39.02) v3(7.05,38.39) v3(7.05,37.75) v3(7.05,37.12) v3(7.05,36.48) v3(7.05,35.72) v3(7.05,22.64) v3(7.05,21.12) v3(7.05,14.26) v3(7.3,43.21) v3(7.3,41.69) v3(7.3,41.05) v3(7.43,13.75) v3(7.43,12.23) v3(7.56,19.85) v3(7.56,15.02) v3(7.68,49.31) v3(7.68,44.48) v3(7.68,40.55) v3(7.68,35.72) v3(7.68,22.64) v3(7.68,21.12) v3(7.68,14.26) v3(7.94,43.21) v3(7.94,41.69) v3(7.94,41.05) v3(8.06,13.75) v3(8.06,12.23) v3(8.19,19.85) v3(8.19,15.02) v3(8.32,49.31) v3(8.32,44.48) v3(8.32,40.55) v3(8.32,35.72) v3(8.32,22.64) v3(8.32,21.12) v3(8.32,14.26) v3(8.57,43.34) v3(8.57,41.05) v3(8.7,13.75) v3(8.7,12.1) v3(8.83,41.82) v3(8.83,19.85) v3(8.83,15.02) v3(8.95,49.31) v3(8.95,44.48) v3(8.95,40.55) v3(8.95,35.72) v3(8.95,22.64) v3(8.95,21.12) v3(8.95,14.26) v3(9.21,41.05) v3(9.33,43.59) v3(9.33,13.75) v3(9.33,11.97) v3(9.46,19.85) v3(9.46,15.02) v3(9.59,49.31) v3(9.59,44.48) v3(9.59,42.07) v3(9.59,40.55) v3(9.59,35.72) v3(9.59,22.64) v3(9.59,21.12) v3(9.59,14.26) v3(9.84,41.05) v3(9.84,11.72) v3(9.97,13.75) v3(10.1,43.98) v3(10.1,19.85) v3(10.1,19.21) v3(10.1,18.58) v3(10.1,16.29) v3(10.1,15.65) v3(10.1,15.02) v3(10.22,49.31) v3(10.22,48.67) v3(10.22,48.04) v3(10.22,45.75) v3(10.22,45.12) v3(10.22,44.48) v3(10.22,42.32) v3(10.22,40.55) v3(10.22,39.91) v3(10.22,39.28) v3(10.22,36.99) v3(10.22,36.48) v3(10.22,35.97) v3(10.22,31.53) v3(10.22,22.64) v3(10.22,21.12) v3(10.22,14.26) v3(10.22,13.24) v3(10.48,41.05) v3(10.48,11.46) v3(10.6,13.75) v3(10.73,48.04) v3(10.73,45.75) v3(10.73,31.53) v3(10.73,18.58) v3(10.73,16.29) v3(10.86,44.61) v3(10.86,42.71) v3(10.86,40.55) v3(10.86,39.28) v3(10.86,36.99) v3(10.86,22.64) v3(10.86,21.12) v3(10.86,14.26) v3(10.86,12.99) v3(10.98,32.04) v3(10.98,31.02) v3(10.98,11.08) v3(11.11,41.05) v3(11.24,47.66) v3(11.24,46.13) v3(11.24,37.37) v3(11.24,31.53) v3(11.24,16.67) v3(11.24,13.75) v3(11.37,39.4) v3(11.37,38.9) v3(11.37,18.32) v3(11.49,43.21) v3(11.49,40.55) v3(11.49,32.04) v3(11.49,31.02) v3(11.49,22.64) v3(11.49,21.12) v3(11.49,14.26) v3(11.49,12.61) v3(11.49,10.7) v3(11.62,45.12) v3(11.75,41.05) v3(11.75,31.53) v3(11.87,47.66) v3(11.87,46.13) v3(11.87,37.37) v3(11.87,16.67) v3(11.87,13.75) v3(12,38.9) v3(12,31.02) v3(12,18.32) v3(12,10.19) v3(12.13,43.72) v3(12.13,40.55) v3(12.13,22.64) v3(12.13,21.12) v3(12.13,14.26) v3(12.13,12.23) v3(12.25,31.53) v3(12.38,41.05) v3(12.51,47.66) v3(12.51,46.13) v3(12.51,45.5) v3(12.51,37.37) v3(12.51,16.67) v3(12.51,13.75) v3(12.51,9.81) v3(12.64,38.9) v3(12.64,18.32) v3(12.64,11.72) v3(12.76,40.55) v3(12.76,22.64) v3(12.76,21.12) v3(12.76,14.26) v3(12.89,44.1) v3(13.02,41.05) v3(13.02,9.43) v3(13.14,47.66) v3(13.14,46.13) v3(13.14,37.37) v3(13.14,16.67) v3(13.14,13.75) v3(13.14,11.21) v3(13.27,38.9) v3(13.27,18.32) v3(13.4,40.55) v3(13.4,22.64) v3(13.4,21.12) v3(13.4,14.26) v3(13.65,41.05) v3(13.65,10.83) v3(13.65,9.05) v3(13.78,47.66) v3(13.78,45.88) v3(13.78,44.23) v3(13.78,37.37) v3(13.78,16.67) v3(13.78,13.75) v3(13.91,38.9) v3(13.91,18.32) v3(14.03,40.55) v3(14.03,22.64) v3(14.03,21.12) v3(14.03,14.26) v3(14.29,41.05) v3(14.29,10.45) v3(14.29,8.8) v3(14.41,47.66) v3(14.41,45.88) v3(14.41,37.37) v3(14.41,16.67) v3(14.41,13.75) v3(14.54,44.23) v3(14.54,38.9) v3(14.54,18.32) v3(14.67,40.55) v3(14.67,22.64) v3(14.67,21.12) v3(14.67,14.26) v3(14.92,41.05) v3(14.92,10.19) v3(14.92,8.54) v3(15.05,47.66) v3(15.05,45.88) v3(15.05,37.37) v3(15.05,16.67) v3(15.05,13.75) v3(15.18,44.23) v3(15.18,38.9) v3(15.18,18.32) v3(15.3,40.55) v3(15.3,22.64) v3(15.3,21.12) v3(15.3,14.26) v3(15.56,41.05) v3(15.56,8.42) v3(15.68,47.66) v3(15.68,45.88) v3(15.68,37.37) v3(15.68,16.67) v3(15.68,13.75) v3(15.68,9.94) v3(15.81,44.23) v3(15.81,38.9) v3(15.81,18.32) v3(15.94,40.55) v3(15.94,22.64) v3(15.94,21.12) v3(15.94,14.26) v3(16.19,41.05) v3(16.32,47.66) v3(16.32,45.88) v3(16.32,37.37) v3(16.32,16.67) v3(16.32,13.75) v3(16.32,9.81) v3(16.32,8.29) v3(16.45,44.23) v3(16.45,38.9) v3(16.45,18.32) v3(16.57,40.55) v3(16.57,22.64) v3(16.57,21.12) v3(16.57,14.26) v3(16.83,41.05) v3(16.95,47.66) v3(16.95,45.88) v3(16.95,37.37) v3(16.95,16.67) v3(16.95,13.75) v3(16.95,9.81) v3(16.95,8.29) v3(17.08,44.23) v3(17.08,38.9) v3(17.08,18.32) v3(17.21,40.55) v3(17.21,22.64) v3(17.21,21.12) v3(17.21,14.26) v3(17.46,41.05) v3(17.59,47.66) v3(17.59,45.88) v3(17.59,37.37) v3(17.59,16.67) v3(17.59,13.75) v3(17.59,9.81) v3(17.59,8.29) v3(17.72,44.23) v3(17.72,38.9) v3(17.72,18.32) v3(17.84,40.55) v3(17.84,22.64) v3(17.84,21.12) v3(17.84,14.26) v3(18.1,41.05) v3(18.22,47.66) v3(18.22,45.88) v3(18.22,37.37) v3(18.22,16.67) v3(18.22,13.75) v3(18.22,9.81) v3(18.22,8.29) v3(18.35,44.23) v3(18.35,38.9) v3(18.35,18.32) v3(18.48,40.55) v3(18.48,22.64) v3(18.48,21.12) v3(18.48,14.26) v3(18.73,41.05) v3(18.86,47.66) v3(18.86,45.88) v3(18.86,37.37) v3(18.86,16.67) v3(18.86,13.75) v3(18.86,9.81) v3(18.86,8.29) v3(18.99,44.23) v3(18.99,38.9) v3(18.99,18.32) v3(19.11,40.55) v3(19.11,22.64) v3(19.11,21.12) v3(19.11,14.26) v3(19.37,41.05) v3(19.49,47.66) v3(19.49,45.88) v3(19.49,37.37) v3(19.49,16.67) v3(19.49,13.75) v3(19.49,9.81) v3(19.49,8.29) v3(19.62,44.23) v3(19.62,38.9) v3(19.62,18.32) v3(19.75,40.55) v3(19.75,22.64) v3(19.75,21.12) v3(19.75,14.26) v3(20,41.05) v3(20.13,47.66) v3(20.13,45.88) v3(20.13,37.37) v3(20.13,16.67) v3(20.13,13.75) v3(20.13,9.81) v3(20.13,8.29) v3(20.26,44.23) v3(20.26,38.9) v3(20.26,18.32) v3(20.38,40.55) v3(20.38,22.64) v3(20.38,21.12) v3(20.38,14.26) v3(20.64,41.05) v3(20.76,47.66) v3(20.76,45.88) v3(20.76,37.37) v3(20.76,16.67) v3(20.76,13.75) v3(20.76,9.81) v3(20.76,8.29) v3(20.89,44.23) v3(20.89,38.9) v3(20.89,18.32) v3(21.02,40.55) v3(21.02,22.64) v3(21.02,21.12) v3(21.02,14.26) v3(21.27,41.05) v3(21.4,47.66) v3(21.4,45.88) v3(21.4,37.37) v3(21.4,36.74) v3(21.4,16.67) v3(21.4,13.75) v3(21.4,10.45) v3(21.4,9.81) v3(21.4,8.29) v3(21.4,7.65) v3(21.53,44.23) v3(21.53,39.53) v3(21.53,38.9) v3(21.53,23.15) v3(21.53,20.48) v3(21.53,18.32) v3(21.65,40.55) v3(21.65,14.26) v3(21.78,48.29) v3(21.91,41.05) v3(22.03,45.63) v3(22.03,36.74) v3(22.03,16.67) v3(22.03,13.75) v3(22.03,10.45) v3(22.03,7.65) v3(22.16,44.23) v3(22.16,39.53) v3(22.16,23.15) v3(22.16,20.48) v3(22.16,18.32) v3(22.29,40.55) v3(22.29,14.26) v3(22.41,48.29) v3(22.54,41.05) v3(22.67,45.63) v3(22.67,36.74) v3(22.67,16.67) v3(22.67,13.75) v3(22.67,10.45) v3(22.67,7.65) v3(22.8,44.23) v3(22.8,39.53) v3(22.8,23.15) v3(22.8,20.48) v3(22.8,18.32) v3(22.92,40.55) v3(22.92,14.26) v3(23.05,48.29) v3(23.05,9.81) v3(23.18,41.05) v3(23.18,22.64) v3(23.18,21.12) v3(23.3,45.88) v3(23.3,36.74) v3(23.3,16.67) v3(23.3,13.75) v3(23.3,10.45) v3(23.3,8.29) v3(23.3,7.65) v3(23.43,44.23) v3(23.43,39.53) v3(23.43,38.9) v3(23.43,18.32) v3(23.56,40.55) v3(23.56,14.26) v3(23.68,48.29) v3(23.68,47.66) v3(23.68,37.37) v3(23.68,9.81) v3(23.81,41.05) v3(23.81,22.64) v3(23.81,21.12) v3(23.94,45.88) v3(23.94,16.67) v3(23.94,13.75) v3(23.94,8.29) v3(24.07,44.23) v3(24.07,38.9) v3(24.07,18.32) v3(24.19,40.55) v3(24.19,32.04) v3(24.19,31.02) v3(24.19,14.26) v3(24.32,47.66) v3(24.32,37.37) v3(24.32,9.81) v3(24.45,41.05) v3(24.45,31.53) v3(24.45,22.64) v3(24.45,21.12) v3(24.57,45.88) v3(24.57,16.67) v3(24.57,13.75) v3(24.57,8.29) v3(24.7,44.23) v3(24.7,38.9) v3(24.7,32.04) v3(24.7,31.02) v3(24.7,18.32) v3(24.83,40.55) v3(24.83,14.26) v3(24.95,37.37) v3(24.95,31.53) v3(24.95,9.81) v3(25.08,41.05) v3(25.08,22.64) v3(25.08,21.12) v3(25.21,47.79) v3(25.21,45.88) v3(25.21,16.67) v3(25.21,13.75) v3(25.21,8.29) v3(25.34,44.23) v3(25.34,38.9) v3(25.34,18.32) v3(25.46,40.55) v3(25.46,14.26) v3(25.59,37.37) v3(25.59,9.81) v3(25.72,41.05) v3(25.72,22.64) v3(25.72,21.12) v3(25.84,46.13) v3(25.84,16.67) v3(25.84,13.75) v3(25.84,8.29) v3(25.97,48.17) v3(25.97,44.23) v3(25.97,38.9) v3(25.97,18.32) v3(26.1,40.55) v3(26.1,14.26) v3(26.22,37.37) v3(26.22,9.81) v3(26.35,45.88) v3(26.35,41.05) v3(26.35,22.64) v3(26.35,21.12) v3(26.48,46.64) v3(26.48,16.67) v3(26.48,13.75) v3(26.48,8.29) v3(26.61,48.67) v3(26.61,44.23) v3(26.61,38.9) v3(26.61,18.32) v3(26.73,40.55) v3(26.73,14.26) v3(26.86,37.37) v3(26.86,9.81) v3(26.99,45.88) v3(26.99,41.05) v3(26.99,22.64) v3(26.99,21.12) v3(27.11,49.18) v3(27.11,47.02) v3(27.11,16.67) v3(27.11,13.75) v3(27.11,8.29) v3(27.24,44.23) v3(27.24,38.9) v3(27.24,18.32) v3(27.37,40.55) v3(27.37,14.26) v3(27.49,37.37) v3(27.49,9.81) v3(27.62,49.69) v3(27.62,47.53) v3(27.62,45.88) v3(27.62,41.05) v3(27.62,22.64) v3(27.62,21.12) v3(27.75,16.67) v3(27.75,13.75) v3(27.75,8.29) v3(27.88,44.23) v3(27.88,38.9) v3(27.88,18.32) v3(28,40.55) v3(28,14.26) v3(28.13,48.04) v3(28.13,37.37) v3(28.13,9.81) v3(28.26,50.2) v3(28.26,45.88) v3(28.26,41.05) v3(28.26,22.64) v3(28.26,21.12) v3(28.38,16.67) v3(28.38,13.75) v3(28.38,8.29) v3(28.51,44.23) v3(28.51,38.9) v3(28.51,18.32) v3(28.64,48.55) v3(28.64,40.55) v3(28.64,14.26) v3(28.76,37.37) v3(28.76,9.81) v3(28.89,50.58) v3(28.89,45.88) v3(28.89,41.05) v3(28.89,22.64) v3(28.89,21.12) v3(29.02,16.67) v3(29.02,13.75) v3(29.02,8.29) v3(29.15,44.23) v3(29.15,38.9) v3(29.15,18.32) v3(29.27,49.06) v3(29.27,40.55) v3(29.27,14.26) v3(29.4,37.37) v3(29.4,9.81) v3(29.53,45.88) v3(29.53,41.05) v3(29.53,22.64) v3(29.53,21.12) v3(29.65,16.67) v3(29.65,13.75) v3(29.65,8.29) v3(29.78,50.83) v3(29.78,44.23) v3(29.78,38.9) v3(29.78,18.32) v3(29.91,40.55) v3(29.91,14.26) v3(30.03,49.31) v3(30.03,37.37) v3(30.03,32.04) v3(30.03,31.02) v3(30.03,9.81) v3(30.16,45.88) v3(30.16,41.05) v3(30.16,22.64) v3(30.16,21.12) v3(30.29,31.53) v3(30.29,16.67) v3(30.29,13.75) v3(30.29,8.29) v3(30.42,44.23) v3(30.42,38.9) v3(30.42,18.32) v3(30.54,50.83) v3(30.54,40.55) v3(30.54,32.04) v3(30.54,31.02) v3(30.54,14.26) v3(30.67,37.37) v3(30.67,9.81) v3(30.8,49.31) v3(30.8,45.88) v3(30.8,41.05) v3(30.8,31.53) v3(30.8,22.64) v3(30.8,21.12) v3(30.92,16.67) v3(30.92,13.75) v3(30.92,8.29) v3(31.05,44.23) v3(31.05,38.9) v3(31.05,32.04) v3(31.05,31.02) v3(31.05,18.32) v3(31.18,51.21) v3(31.18,40.55) v3(31.18,14.26) v3(31.3,48.93) v3(31.3,37.37) v3(31.3,31.53) v3(31.3,9.81) v3(31.43,45.88) v3(31.43,41.05) v3(31.43,22.89) v3(31.43,20.86) v3(31.56,32.04) v3(31.56,31.02) v3(31.56,16.67) v3(31.56,13.75) v3(31.56,8.29) v3(31.69,44.23) v3(31.69,38.9) v3(31.69,18.32) v3(31.81,51.21) v3(31.81,40.55) v3(31.81,31.53) v3(31.81,14.26) v3(31.94,48.93) v3(31.94,37.37) v3(31.94,9.81) v3(32.07,45.88) v3(32.07,41.05) v3(32.07,32.04) v3(32.07,31.02) v3(32.07,22.89) v3(32.07,20.86) v3(32.19,16.67) v3(32.19,13.75) v3(32.19,8.29) v3(32.32,44.23) v3(32.32,38.9) v3(32.32,31.53) v3(32.32,18.32) v3(32.45,51.21) v3(32.45,40.55) v3(32.45,14.26) v3(32.57,48.93) v3(32.57,37.37) v3(32.57,32.04) v3(32.57,31.02) v3(32.57,9.81) v3(32.7,45.88) v3(32.7,41.05) v3(32.7,22.89) v3(32.7,20.86) v3(32.83,31.53) v3(32.83,16.67) v3(32.83,13.75) v3(32.83,8.29) v3(32.96,44.23) v3(32.96,38.9) v3(32.96,18.32) v3(33.08,51.21) v3(33.08,40.55) v3(33.08,32.04) v3(33.08,31.02) v3(33.08,14.26) v3(33.21,48.93) v3(33.21,37.37) v3(33.21,9.81) v3(33.34,45.88) v3(33.34,41.05) v3(33.34,31.53) v3(33.34,22.89) v3(33.34,20.86) v3(33.46,16.67) v3(33.46,13.75) v3(33.46,8.29) v3(33.59,44.23) v3(33.59,38.9) v3(33.59,32.04) v3(33.59,31.02) v3(33.59,18.32) v3(33.72,51.21) v3(33.72,40.55) v3(33.72,20.35) v3(33.72,19.72) v3(33.72,14.26) v3(33.84,48.93) v3(33.84,37.37) v3(33.84,31.53) v3(33.97,51.85) v3(33.97,45.88) v3(33.97,41.05) v3(33.97,22.89) v3(33.97,9.81) v3(34.1,16.67) v3(34.1,13.75) v3(34.1,8.29) v3(34.23,44.23) v3(34.23,38.9) v3(34.23,18.32) v3(34.35,40.55) v3(34.35,19.72) v3(34.35,14.26) v3(34.48,52.23) v3(34.48,48.93) v3(34.48,37.37) v3(34.61,45.88) v3(34.61,41.05) v3(34.61,22.89) v3(34.61,9.81) v3(34.73,16.67) v3(34.73,13.75) v3(34.73,8.29) v3(34.86,44.23) v3(34.86,38.9) v3(34.86,18.32) v3(34.99,40.55) v3(34.99,19.72) v3(34.99,14.26) v3(35.11,52.23) v3(35.11,48.93) v3(35.11,45.88) v3(35.11,37.37) v3(35.24,41.05) v3(35.24,22.89) v3(35.24,9.81) v3(35.37,16.67) v3(35.37,13.75) v3(35.37,8.29) v3(35.5,44.23) v3(35.5,38.9) v3(35.5,18.32) v3(35.62,40.55) v3(35.62,20.99) v3(35.62,20.35) v3(35.62,19.72) v3(35.62,14.26) v3(35.75,52.23) v3(35.75,51.6) v3(35.75,50.96) v3(35.75,48.93) v3(35.75,45.88) v3(35.75,37.37) v3(35.88,41.05) v3(35.88,9.81) v3(36,16.67) v3(36,13.75) v3(36,8.29) v3(36.13,44.23) v3(36.13,38.9) v3(36.13,27.34) v3(36.13,26.7) v3(36.13,26.07) v3(36.13,25.43) v3(36.13,24.8) v3(36.13,24.16) v3(36.13,23.53) v3(36.13,18.32) v3(36.26,40.55) v3(36.26,20.48) v3(36.26,14.26) v3(36.38,55.66) v3(36.38,55.02) v3(36.38,54.39) v3(36.38,53.75) v3(36.38,53.12) v3(36.38,52.48) v3(36.38,51.85) v3(36.38,48.8) v3(36.38,45.88) v3(36.38,37.37) v3(36.51,41.05) v3(36.51,23.02) v3(36.51,9.81) v3(36.64,16.67) v3(36.64,13.75) v3(36.64,8.29) v3(36.77,51.34) v3(36.77,38.9) v3(36.77,27.34) v3(36.77,26.7) v3(36.77,26.07) v3(36.77,25.43) v3(36.77,24.8) v3(36.77,24.16) v3(36.77,23.53) v3(36.77,18.32) v3(36.89,44.23) v3(36.89,40.55) v3(36.89,20.48) v3(36.89,14.26) v3(37.02,55.66) v3(37.02,55.02) v3(37.02,54.39) v3(37.02,53.75) v3(37.02,53.12) v3(37.02,52.48) v3(37.02,51.85) v3(37.02,48.8) v3(37.02,45.88) v3(37.02,37.37) v3(37.15,41.05) v3(37.15,9.81) v3(37.27,16.67) v3(37.27,13.75) v3(37.27,8.29) v3(37.4,38.9) v3(37.4,27.34) v3(37.4,26.7) v3(37.4,26.07) v3(37.4,25.43) v3(37.4,24.8) v3(37.4,24.16) v3(37.4,23.53) v3(37.4,18.32) v3(37.53,44.23) v3(37.53,40.55) v3(37.53,20.48) v3(37.53,14.26) v3(37.65,55.66) v3(37.65,55.02) v3(37.65,54.39) v3(37.65,53.75) v3(37.65,53.12) v3(37.65,52.48) v3(37.65,51.85) v3(37.65,48.8) v3(37.65,45.88) v3(37.65,37.37) v3(37.65,22.89) v3(37.65,22.26) v3(37.65,21.62) v3(37.65,20.99) v3(37.78,41.05) v3(37.78,9.81) v3(37.91,51.21) v3(37.91,50.58) v3(37.91,49.94) v3(37.91,49.31) v3(37.91,16.67) v3(37.91,13.75) v3(37.91,8.29) v3(38.04,38.9) v3(38.04,18.32) v3(38.16,44.23) v3(38.16,40.55) v3(38.16,27.34) v3(38.16,26.7) v3(38.16,26.07) v3(38.16,25.43) v3(38.16,24.8) v3(38.16,24.16) v3(38.16,23.53) v3(38.16,22.89) v3(38.16,22.26) v3(38.16,21.62) v3(38.16,20.99) v3(38.16,20.48) v3(38.16,14.26) v3(38.29,48.8) v3(38.29,45.88) v3(38.29,37.37) v3(38.42,56.93) v3(38.42,56.29) v3(38.42,55.66) v3(38.42,55.02) v3(38.42,54.39) v3(38.42,53.75) v3(38.42,53.12) v3(38.42,52.48) v3(38.42,51.85) v3(38.42,51.21) v3(38.42,50.58) v3(38.42,49.94) v3(38.42,49.31) v3(38.42,41.05) v3(38.42,9.81) v3(38.54,16.67) v3(38.54,13.75) v3(38.54,8.29) v3(38.67,38.9) v3(38.67,22.89) v3(38.67,22.26) v3(38.67,21.62) v3(38.67,20.99) v3(38.67,18.32) v3(38.8,44.23) v3(38.8,40.55) v3(38.8,20.48) v3(38.8,14.26) v3(38.92,51.21) v3(38.92,50.58) v3(38.92,49.94) v3(38.92,49.31) v3(38.92,48.8) v3(38.92,45.88) v3(38.92,37.37) v3(38.92,27.34) v3(38.92,26.7) v3(38.92,26.07) v3(38.92,25.43) v3(38.92,24.8) v3(38.92,24.16) v3(38.92,23.53) v3(39.05,41.05) v3(39.05,9.81) v3(39.18,55.66) v3(39.18,55.02) v3(39.18,54.39) v3(39.18,53.75) v3(39.18,53.12) v3(39.18,52.48) v3(39.18,51.85) v3(39.18,16.67) v3(39.18,13.75) v3(39.18,8.29) v3(39.31,38.9) v3(39.31,18.32) v3(39.43,44.23) v3(39.43,40.55) v3(39.43,20.48) v3(39.43,14.26) v3(39.56,48.8) v3(39.56,45.88) v3(39.56,37.37) v3(39.56,27.34) v3(39.56,26.7) v3(39.56,26.07) v3(39.56,25.43) v3(39.56,24.8) v3(39.56,24.16) v3(39.56,23.53) v3(39.69,41.05) v3(39.69,9.81) v3(39.81,55.66) v3(39.81,55.02) v3(39.81,54.39) v3(39.81,53.75) v3(39.81,53.12) v3(39.81,52.48) v3(39.81,51.85) v3(39.81,23.02) v3(39.81,16.67) v3(39.81,13.75) v3(39.81,8.29) v3(39.94,38.9) v3(39.94,18.32) v3(40.07,51.34) v3(40.07,44.23) v3(40.07,40.55) v3(40.07,20.48) v3(40.07,14.26) v3(40.19,48.8) v3(40.19,45.88) v3(40.19,37.37) v3(40.19,27.34) v3(40.19,26.7) v3(40.19,26.07) v3(40.19,25.43) v3(40.19,24.8) v3(40.19,24.16) v3(40.19,23.53) v3(40.32,41.05) v3(40.32,9.81) v3(40.45,55.02) v3(40.45,54.39) v3(40.45,53.75) v3(40.45,53.12) v3(40.45,52.48) v3(40.45,51.85) v3(40.45,16.67) v3(40.45,13.75) v3(40.45,8.29) v3(40.58,38.9) v3(40.58,28.48) v3(40.58,27.85) v3(40.58,18.32) v3(40.7,44.23) v3(40.7,40.55) v3(40.7,20.48) v3(40.7,14.26) v3(40.83,48.8) v3(40.83,45.88) v3(40.83,37.37) v3(40.96,49.44) v3(40.96,41.05) v3(40.96,9.81) v3(41.08,16.67) v3(41.08,13.75) v3(41.08,8.29) v3(41.21,38.9) v3(41.21,20.86) v3(41.21,18.32) v3(41.34,44.23) v3(41.34,40.55) v3(41.34,14.26) v3(41.46,45.88) v3(41.46,37.37) v3(41.59,49.18) v3(41.59,41.05) v3(41.59,9.81) v3(41.72,16.67) v3(41.72,13.75) v3(41.72,8.29) v3(41.85,38.9) v3(41.85,20.86) v3(41.85,18.32) v3(41.97,44.23) v3(41.97,40.55) v3(41.97,14.26) v3(42.1,45.88) v3(42.1,37.37) v3(42.23,49.18) v3(42.23,41.05) v3(42.23,9.81) v3(42.35,16.67) v3(42.35,13.75) v3(42.35,8.29) v3(42.48,38.9) v3(42.48,20.86) v3(42.48,18.32) v3(42.61,44.23) v3(42.61,40.55) v3(42.61,14.26) v3(42.73,45.88) v3(42.73,37.37) v3(42.86,49.18) v3(42.86,41.05) v3(42.86,9.81) v3(42.99,16.67) v3(42.99,13.75) v3(42.99,8.29) v3(43.12,38.9) v3(43.12,20.86) v3(43.12,18.32) v3(43.24,44.23) v3(43.24,40.55) v3(43.24,14.26) v3(43.37,45.88) v3(43.37,37.37) v3(43.5,54.26) v3(43.5,52.36) v3(43.5,49.18) v3(43.5,41.05) v3(43.5,9.81) v3(43.62,16.67) v3(43.62,13.75) v3(43.62,8.29) v3(43.75,38.9) v3(43.75,20.86) v3(43.75,18.32) v3(43.88,44.23) v3(43.88,40.55) v3(43.88,14.26) v3(44,45.88) v3(44,37.37) v3(44.13,54.26) v3(44.13,52.36) v3(44.13,49.18) v3(44.13,41.05) v3(44.13,9.81) v3(44.26,53.63) v3(44.26,52.99) v3(44.26,16.67) v3(44.26,13.75) v3(44.26,8.29) v3(44.39,38.9) v3(44.39,25.43) v3(44.39,23.27) v3(44.39,22.64) v3(44.39,20.86) v3(44.39,18.32) v3(44.51,56.17) v3(44.51,44.23) v3(44.51,40.55) v3(44.51,14.26) v3(44.51,7.65) v3(44.51,7.02) v3(44.51,6.38) v3(44.51,5.75) v3(44.64,45.88) v3(44.64,37.37) v3(44.77,55.41) v3(44.77,52.36) v3(44.77,51.72) v3(44.77,50.96) v3(44.77,49.44) v3(44.77,41.05) v3(44.77,9.81) v3(44.89,16.67) v3(44.89,13.75) v3(44.89,8.29) v3(45.02,38.9) v3(45.02,22.64) v3(45.02,21.12) v3(45.02,18.32) v3(45.02,10.45) v3(45.15,44.23) v3(45.15,40.55) v3(45.15,14.26) v3(45.15,5.75) v3(45.27,45.88) v3(45.27,37.37) v3(45.27,25.81) v3(45.4,50.96) v3(45.4,49.44) v3(45.4,41.05) v3(45.53,16.67) v3(45.53,13.75) v3(45.53,7.78) v3(45.66,38.9) v3(45.66,22.64) v3(45.66,21.12) v3(45.66,18.32) v3(45.66,10.45) v3(45.78,56.17) v3(45.78,44.23) v3(45.78,40.55) v3(45.78,14.26) v3(45.78,5.75) v3(45.91,45.88) v3(45.91,37.37) v3(46.04,50.96) v3(46.04,49.44) v3(46.04,41.05) v3(46.16,58.07) v3(46.16,56.8) v3(46.16,16.67) v3(46.16,13.75) v3(46.16,7.78) v3(46.29,38.9) v3(46.29,25.81) v3(46.29,22.64) v3(46.29,21.12) v3(46.29,18.32) v3(46.29,10.45) v3(46.42,44.23) v3(46.42,40.55) v3(46.42,14.26) v3(46.42,5.75) v3(46.54,45.88) v3(46.54,37.37) v3(46.67,50.96) v3(46.67,49.44) v3(46.67,41.05) v3(46.8,24.42) v3(46.8,16.67) v3(46.8,13.75) v3(46.8,7.78) v3(46.93,38.9) v3(46.93,22.64) v3(46.93,21.12) v3(46.93,18.32) v3(46.93,10.45) v3(47.05,44.23) v3(47.05,40.55) v3(47.05,14.26) v3(47.05,5.75) v3(47.18,45.88) v3(47.18,37.37) v3(47.18,25.81) v3(47.31,50.96) v3(47.31,49.44) v3(47.31,41.05) v3(47.43,16.67) v3(47.43,13.75) v3(47.43,7.78) v3(47.56,38.9) v3(47.56,22.64) v3(47.56,21.12) v3(47.56,18.32) v3(47.56,10.45) v3(47.56,9.81) v3(47.69,44.23) v3(47.69,40.55) v3(47.69,14.26) v3(47.69,8.29) v3(47.69,5.75) v3(47.81,45.88) v3(47.81,37.37) v3(47.94,50.96) v3(47.94,49.44) v3(47.94,41.05) v3(48.07,16.67) v3(48.07,13.75) v3(48.13,9.81) v3(48.2,38.9) v3(48.2,22.64) v3(48.2,21.12) v3(48.2,18.32) v3(48.32,44.23) v3(48.32,40.55) v3(48.32,14.26) v3(48.26,8.29) v3(48.32,7.65) v3(48.32,7.02) v3(48.32,6.38) v3(48.32,5.75) v3(48.45,45.88) v3(48.45,37.37) v3(48.58,50.96) v3(48.58,49.44) v3(48.58,41.05) v3(48.7,16.67) v3(48.7,13.75) v3(48.7,9.81) v3(48.83,38.9) v3(48.83,22.64) v3(48.83,21.12) v3(48.83,18.32) v3(48.83,8.29) v3(48.96,44.23) v3(48.96,40.55) v3(48.96,25.81) v3(48.96,14.26) v3(49.08,45.88) v3(49.08,37.37) v3(49.21,50.96) v3(49.21,49.44) v3(49.21,41.05) v3(49.21,9.81) v3(49.34,31.66) v3(49.34,16.67) v3(49.34,13.75) v3(49.47,38.9) v3(49.47,22.64) v3(49.47,21.12) v3(49.47,18.32) v3(49.47,8.29) v3(49.59,44.23) v3(49.59,40.55) v3(49.59,32.16) v3(49.59,31.15) v3(49.59,27.97) v3(49.59,27.21) v3(49.59,14.26) v3(49.72,45.88) v3(49.72,37.37) v3(49.85,50.96) v3(49.85,49.44) v3(49.85,41.05) v3(49.85,31.66) v3(49.85,9.81) v3(49.97,16.67) v3(49.97,13.75) v3(50.1,38.9) v3(50.1,22.64) v3(50.1,21.12) v3(50.1,18.32) v3(50.1,8.29) v3(50.23,44.23) v3(50.23,40.55) v3(50.23,14.26) v3(50.35,45.88) v3(50.35,37.37) v3(50.48,50.96) v3(50.48,49.44) v3(50.48,41.05) v3(50.48,9.81) v3(50.61,16.67) v3(50.61,13.75) v3(50.74,38.9) v3(50.74,22.64) v3(50.74,21.12) v3(50.74,18.32) v3(50.74,8.29) v3(50.86,44.23) v3(50.86,40.55) v3(50.86,36.74) v3(50.86,36.1) v3(50.86,35.47) v3(50.86,34.83) v3(50.86,14.26) v3(50.99,45.88) v3(50.99,37.37) v3(51.12,50.96) v3(51.12,49.44) v3(51.12,41.05) v3(51.12,9.81) v3(51.24,16.67) v3(51.24,13.75) v3(51.37,39.53) v3(51.37,38.9) v3(51.37,22.64) v3(51.37,21.12) v3(51.37,18.32) v3(51.37,8.29) v3(51.5,44.23) v3(51.5,40.55) v3(51.5,14.26) v3(51.62,37.37) v3(51.62,36.86) v3(51.62,34.83) v3(51.75,50.96) v3(51.75,49.44) v3(51.75,41.05) v3(51.75,9.81) v3(51.88,16.67) v3(51.88,13.75) v3(52.01,39.53) v3(52.01,22.64) v3(52.01,21.12) v3(52.01,18.32) v3(52.01,8.29) v3(52.13,44.23) v3(52.13,40.55) v3(52.13,14.26) v3(52.26,45.88) v3(52.26,36.86) v3(52.39,50.96) v3(52.39,49.44) v3(52.39,41.05) v3(52.39,34.83) v3(52.39,9.81) v3(52.51,16.67) v3(52.51,13.75) v3(52.64,39.53) v3(52.64,22.64) v3(52.64,21.12) v3(52.64,18.32) v3(52.64,8.29) v3(52.77,44.23) v3(52.77,40.55) v3(52.77,14.26) v3(52.89,46.01) v3(52.89,36.86) v3(53.02,50.96) v3(53.02,49.44) v3(53.02,41.05) v3(53.02,16.29) v3(53.02,9.81) v3(53.15,34.83) v3(53.15,18.58) v3(53.15,13.75) v3(53.28,47.66) v3(53.28,47.02) v3(53.28,46.39) v3(53.28,43.85) v3(53.28,39.53) v3(53.28,22.64) v3(53.28,21.12) v3(53.28,15.65) v3(53.28,15.02) v3(53.28,8.29) v3(53.4,40.55) v3(53.4,14.26) v3(53.53,36.86) v3(53.66,50.96) v3(53.66,49.44) v3(53.66,41.05) v3(53.66,9.81) v3(53.78,18.58) v3(53.78,13.75) v3(53.91,47.79) v3(53.91,43.85) v3(53.91,39.53) v3(53.91,38.9) v3(53.91,37.37) v3(53.91,34.83) v3(53.91,22.64) v3(53.91,21.12) v3(53.91,8.29) v3(54.04,40.55) v3(54.04,14.26) v3(54.29,50.96) v3(54.29,49.44) v3(54.29,41.05) v3(54.29,9.81) v3(54.42,18.58) v3(54.42,13.75) v3(54.55,43.85) v3(54.55,38.9) v3(54.55,37.37) v3(54.55,22.64) v3(54.55,21.12) v3(54.55,8.29) v3(54.67,40.55) v3(54.67,36.74) v3(54.67,36.1) v3(54.67,35.47) v3(54.67,34.83) v3(54.67,14.26) v3(54.93,50.96) v3(54.93,49.44) v3(54.93,41.05) v3(54.93,9.81) v3(55.05,18.58) v3(55.05,13.75) v3(55.18,43.85) v3(55.18,38.9) v3(55.18,37.37) v3(55.18,22.64) v3(55.18,21.12) v3(55.18,8.29) v3(55.31,47.66) v3(55.31,47.02) v3(55.31,46.39) v3(55.31,40.55) v3(55.31,15.65) v3(55.31,15.02) v3(55.31,14.26) v3(55.56,50.96) v3(55.56,49.44) v3(55.56,41.05) v3(55.56,9.81) v3(55.69,18.58) v3(55.69,13.75) v3(55.82,46.39) v3(55.82,43.85) v3(55.82,38.9) v3(55.82,37.37) v3(55.82,22.64) v3(55.82,21.12) v3(55.82,16.04) v3(55.82,8.29) v3(55.94,40.55) v3(55.94,31.66) v3(55.94,14.26) v3(56.2,50.96) v3(56.2,49.44) v3(56.2,41.05) v3(56.2,32.16) v3(56.2,31.15) v3(56.2,9.81) v3(56.32,18.58) v3(56.32,13.75) v3(56.45,46.39) v3(56.45,43.85) v3(56.45,38.9) v3(56.45,37.37) v3(56.45,31.66) v3(56.45,22.64) v3(56.45,21.12) v3(56.45,16.04) v3(56.45,8.29) v3(56.58,40.55) v3(56.58,14.26) v3(56.83,50.96) v3(56.83,49.44) v3(56.83,41.05) v3(56.83,9.81) v3(56.96,18.58) v3(56.96,13.75) v3(57.09,46.39) v3(57.09,43.85) v3(57.09,38.9) v3(57.09,37.37) v3(57.09,22.64) v3(57.09,21.12) v3(57.09,16.04) v3(57.09,8.29) v3(57.21,40.55) v3(57.21,14.26) v3(57.47,50.96) v3(57.47,49.44) v3(57.47,41.05) v3(57.47,9.81) v3(57.59,18.58) v3(57.59,13.75) v3(57.72,46.39) v3(57.72,43.85) v3(57.72,38.9) v3(57.72,37.37) v3(57.72,22.64) v3(57.72,21.12) v3(57.72,16.04) v3(57.72,8.29) v3(57.85,40.55) v3(57.85,14.26) v3(58.1,50.96) v3(58.1,49.44) v3(58.1,41.05) v3(58.1,9.81) v3(58.23,18.58) v3(58.23,13.75) v3(58.36,46.39) v3(58.36,43.85) v3(58.36,38.9) v3(58.36,37.37) v3(58.36,22.64) v3(58.36,21.12) v3(58.36,16.04) v3(58.36,8.29) v3(58.48,40.55) v3(58.48,14.26) v3(58.74,50.96) v3(58.74,49.44) v3(58.74,41.05) v3(58.74,9.81) v3(58.86,18.58) v3(58.86,15.65) v3(58.86,15.02) v3(58.86,13.75) v3(58.99,47.66) v3(58.99,47.02) v3(58.99,46.39) v3(58.99,43.85) v3(58.99,38.9) v3(58.99,37.37) v3(58.99,22.64) v3(58.99,21.12) v3(58.99,8.29) v3(59.12,40.55) v3(59.12,14.26) v3(59.37,50.96) v3(59.37,49.44) v3(59.37,41.05) v3(59.37,9.81) v3(59.5,47.79) v3(59.5,18.58) v3(59.5,13.75) v3(59.63,43.85) v3(59.63,38.9) v3(59.63,37.37) v3(59.63,22.64) v3(59.63,21.12) v3(59.63,8.29) v3(59.75,40.55) v3(59.75,14.26) v3(60.01,50.96) v3(60.01,49.44) v3(60.01,47.79) v3(60.01,41.05) v3(60.01,9.81) v3(60.13,18.58) v3(60.13,13.75) v3(60.26,43.85) v3(60.26,38.9) v3(60.26,37.37) v3(60.26,22.64) v3(60.26,21.12) v3(60.26,8.29) v3(60.39,40.55) v3(60.39,14.26) v3(60.51,47.79) v3(60.64,50.96) v3(60.64,49.44) v3(60.64,41.05) v3(60.64,9.81) v3(60.79,18.55) v3(60.77,13.75) v3(60.9,43.85) v3(60.9,38.9) v3(60.9,37.37) v3(60.9,16.29) v3(60.9,15.65) v3(60.9,15.02) v3(60.9,8.29) v3(61.02,47.53) v3(61.02,46.9) v3(61.02,46.26) v3(61.02,40.55) v3(61.02,14.26) v3(61.28,58.71) v3(61.28,58.07) v3(61.28,57.44) v3(61.28,50.96) v3(61.28,49.44) v3(61.28,41.05) v3(61.27,30.1) v3(61.27,29.46) v3(61.27,28.83) v3(61.27,22.6) v3(61.27,21.08) v3(61.26,18.18) v3(61.29,16.63) v3(61.28,9.81) v3(61.39,45.82) v3(61.42,44.27) v3(61.4,13.75) v3(61.53,48.93) v3(61.53,48.29) v3(61.53,38.9) v3(61.53,37.37) v3(61.52,20.57) v3(61.52,19.94) v3(61.53,8.29) v3(61.66,40.55) v3(61.66,14.26) v3(61.78,55.79) v3(61.78,55.15) v3(61.78,54.52) v3(61.78,53.88) v3(61.78,51.09) v3(61.77,22.73) v3(61.91,41.05) v3(61.89,18.18) v3(61.92,16.63) v3(61.91,9.81) v3(62.04,48.04) v3(62.02,45.82) v3(62.03,19.68) v3(62.04,13.75) v3(62.05,44.27) v3(62.17,38.9) v3(62.17,37.37) v3(62.17,8.29) v3(62.29,40.55) v3(62.29,14.26) v3(62.42,52.99) v3(62.42,52.36) v3(62.42,51.72) v3(62.42,51.09) v3(62.41,24.64) v3(62.41,24) v3(62.41,23.37) v3(62.41,22.73) v3(62.55,41.05) v3(62.53,18.18) v3(62.55,9.81) v3(62.56,16.63) v3(62.67,48.04) v3(62.66,45.82) v3(62.69,44.27) v3(62.66,19.68) v3(62.67,13.75) v3(62.8,38.9) v3(62.8,37.37) v3(62.8,8.29) v3(62.93,40.55) v3(62.93,14.26) v3(63.04,24.64) v3(63.04,22.73) v3(63.05,52.99) v3(63.05,51.09) v3(63.18,41.05) v3(63.16,18.18) v3(63.19,16.63) v3(63.18,9.81) v3(63.31,48.67) v3(63.31,48.04) v3(63.29,45.82) v3(63.32,44.27) v3(63.3,20.32) v3(63.3,19.68) v3(63.31,13.75) v3(63.44,38.9) v3(63.44,37.37) v3(63.44,8.29) v3(63.56,40.55) v3(63.56,14.26) v3(63.69,52.99) v3(63.69,51.09) v3(63.69,49.18) v3(63.69,26.83) v3(63.69,25.18) v3(63.68,24.64) v3(63.68,22.73) v3(63.68,20.83) v3(63.82,41.05) v3(63.8,18.18) v3(63.83,16.63) v3(63.82,9.81) v3(63.93,45.82) v3(63.94,13.75) v3(63.96,44.27) v3(64.07,38.9) v3(64.07,37.37) v3(64.07,8.29) v3(64.2,40.55) v3(64.2,26.83) v3(64.2,25.18) v3(64.2,14.26) v3(64.32,52.99) v3(64.32,51.09) v3(64.32,49.18) v3(64.31,24.64) v3(64.31,22.73) v3(64.31,20.83) v3(64.43,18.18) v3(64.45,41.05) v3(64.46,16.63) v3(64.45,9.81) v3(64.56,45.82) v3(64.59,44.27) v3(64.58,13.75) v3(64.71,38.9) v3(64.71,37.37) v3(64.71,8.29) v3(64.83,40.55) v3(64.83,14.26) v3(64.95,24) v3(64.95,23.37) v3(64.95,22.73) v3(64.95,20.83) v3(64.95,20.19) v3(64.95,19.56) v3(64.96,52.36) v3(64.96,51.72) v3(64.96,51.09) v3(64.96,49.18) v3(64.96,48.55) v3(64.96,47.91) v3(65.09,41.05) v3(65.07,18.18) v3(65.1,16.63) v3(65.09,9.81) v3(65.2,45.82) v3(65.23,44.27) v3(65.21,13.75) v3(65.34,38.9) v3(65.34,37.37) v3(65.34,8.29) v3(65.47,40.55) v3(65.47,14.26) v3(65.59,52.61) v3(65.59,48.55) v3(65.59,47.91) v3(65.58,24.25) v3(65.58,20.19) v3(65.58,19.56) v3(65.72,41.05) v3(65.7,18.18) v3(65.73,16.63) v3(65.72,9.81) v3(65.83,45.82) v3(65.85,13.75) v3(65.86,44.27) v3(65.98,38.9) v3(65.98,37.37) v3(65.98,8.29) v3(66.1,40.55) v3(66.1,14.26) v3(66.23,52.61) v3(66.23,48.55) v3(66.23,47.91) v3(66.22,24.25) v3(66.22,20.19) v3(66.22,19.56) v3(66.34,18.18) v3(66.36,41.05) v3(66.37,16.63) v3(66.36,9.81) v3(66.47,45.82) v3(66.5,44.27) v3(66.48,13.75) v3(66.61,38.9) v3(66.61,37.37) v3(66.61,8.29) v3(66.74,40.55) v3(66.74,14.26) v3(66.86,47.79) v3(66.85,19.43) v3(66.99,41.05) v3(66.97,18.18) v3(67,16.63) v3(66.99,9.81) v3(67.1,45.82) v3(67.13,44.27) v3(67.12,13.75) v3(67.25,38.9) v3(67.25,37.37) v3(67.25,8.29) v3(67.37,40.55) v3(67.37,14.26) v3(67.5,47.79) v3(67.49,19.43) v3(67.63,41.05) v3(67.61,18.18) v3(67.64,16.63) v3(67.63,9.81) v3(67.74,45.82) v3(67.74,29.33) v3(67.74,28.7) v3(67.75,57.69) v3(67.75,57.06) v3(67.77,44.27) v3(67.75,38.9) v3(67.75,13.75) v3(67.88,37.37) v3(67.88,8.29) v3(68.01,40.55) v3(68.01,14.26) v3(68.26,41.05) v3(68.26,38.9) v3(68.26,18.09) v3(68.27,16.63) v3(68.26,9.81) v3(68.37,45.82) v3(68.4,44.27) v3(68.39,13.75) v3(68.52,37.37) v3(68.52,8.29) v3(68.64,40.55) v3(68.64,14.26) v3(68.77,31.66) v3(68.9,41.05) v3(68.87,18.09) v3(68.91,16.63) v3(68.9,9.81) v3(69.01,45.82) v3(69.04,44.27) v3(69.02,32.16) v3(69.02,13.75) v3(69.15,37.37) v3(69.15,8.29) v3(69.28,40.55) v3(69.3,38.9) v3(69.28,14.26) v3(69.53,41.05) v3(69.53,32.16) v3(69.53,18.09) v3(69.54,16.63) v3(69.53,9.81) v3(69.64,45.82) v3(69.67,44.27) v3(69.66,13.75) v3(69.79,57.82) v3(69.79,48.67) v3(69.79,48.04) v3(69.79,37.37) v3(69.79,31.66) v3(69.78,29.46) v3(69.79,20.35) v3(69.79,19.72) v3(69.79,8.29) v3(69.91,40.55) v3(69.86,38.9) v3(69.91,14.26) v3(70.14,18.09) v3(70.17,41.05) v3(70.18,16.63) v3(70.17,9.81) v3(70.29,57.82) v3(70.29,48.67) v3(70.29,48.04) v3(70.28,45.82) v3(70.31,44.27) v3(70.28,29.46) v3(70.29,20.35) v3(70.29,19.72) v3(70.29,13.75) v3(70.42,38.9) v3(70.42,37.37) v3(70.42,8.29) v3(70.55,40.55) v3(70.55,14.26) v3(70.8,41.05) v3(70.8,18.19) v3(70.81,16.69) v3(70.8,9.81) v3(70.93,47.53) v3(70.93,46.77) v3(70.91,45.88) v3(70.94,44.32) v3(70.92,19.17) v3(70.93,13.75) v3(71.06,38.9) v3(71.06,37.37) v3(71.06,8.29) v3(71.18,40.55) v3(71.18,14.26) v3(71.31,30.64) v3(71.44,41.05) v3(71.41,18.35) v3(71.44,16.78) v3(71.44,9.81) v3(71.54,45.98) v3(71.56,47.53) v3(71.57,44.41) v3(71.55,19.17) v3(71.56,13.75) v3(71.69,38.9) v3(71.69,8.29) v3(71.82,40.55) v3(71.82,37.37) v3(71.82,14.26) v3(71.94,30.64) v3(72.03,18.48) v3(72.07,49.94) v3(72.07,49.31) v3(72.07,48.67) v3(72.07,48.04) v3(72.07,41.05) v3(72.06,21.59) v3(72.06,20.95) v3(72.06,20.32) v3(72.06,19.68) v3(72.06,16.9) v3(72.07,9.81) v3(72.16,46.11) v3(72.19,44.53) v3(72.2,13.75) v3(72.33,8.31) v3(72.33,7.04) v3(72.33,6.41) v3(72.33,5.14) v3(72.33,4.5) v3(72.45,40.55) v3(72.45,36.1) v3(72.45,35.47) v3(72.45,34.2) v3(72.45,33.56) v3(72.45,14.26) v3(72.58,49.94) v3(72.58,30.64) v3(72.57,21.59) v3(72.64,18.64) v3(72.71,41.05) v3(72.68,17.04) v3(72.71,9.81) v3(72.77,46.28) v3(72.81,44.68) v3(72.83,13.75) v3(72.96,38.9) v3(73.09,40.55) v3(73.09,33.56) v3(73.09,14.26) v3(73.21,51.6) v3(73.21,49.94) v3(73.21,30.64) v3(73.2,23.24) v3(73.2,21.59) v3(73.25,18.83) v3(73.34,43.72) v3(73.34,42.96) v3(73.34,42.32) v3(73.34,41.69) v3(73.34,41.05) v3(73.29,17.22) v3(73.34,9.81) v3(73.38,46.47) v3(73.42,44.85) v3(73.47,13.75) v3(73.6,38.9) v3(73.72,44.23) v3(73.72,40.55) v3(73.72,33.56) v3(73.72,14.26) v3(73.85,51.6) v3(73.85,49.94) v3(73.84,23.24) v3(73.84,21.59) v3(73.84,19.06) v3(73.9,17.42) v3(73.98,55.28) v3(73.98,54.14) v3(73.98,53.5) v3(73.98,49.31) v3(73.98,48.67) v3(73.97,46.69) v3(74.02,45.05) v3(73.98,42.96) v3(73.98,42.32) v3(73.98,41.69) v3(73.98,41.05) v3(73.98,30.64) v3(73.97,27.05) v3(73.97,25.78) v3(73.97,25.14) v3(73.97,20.95) v3(73.97,20.32) v3(73.98,9.81) v3(74.1,43.72) v3(74.1,13.75) v3(74.23,38.9) v3(74.36,44.23) v3(74.43,19.31) v3(74.36,14.26) v3(74.48,53.25) v3(74.48,52.61) v3(74.48,51.98) v3(74.47,24.89) v3(74.47,24.25) v3(74.47,23.62) v3(74.49,17.65) v3(74.61,48.67) v3(74.55,46.94) v3(74.62,45.28) v3(74.61,41.69) v3(74.61,41.05) v3(74.61,40.55) v3(74.61,30.64) v3(74.6,20.32) v3(74.61,9.81) v3(74.74,43.72) v3(74.74,13.75) v3(74.87,40.04) v3(74.87,38.9) v3(74.87,31.66) v3(74.99,44.23) v3(74.99,19.59) v3(74.99,14.26) v3(75.12,53.25) v3(75.12,51.98) v3(75.12,47.22) v3(75.12,32.16) v3(75.12,31.15) v3(75.11,24.89) v3(75.11,23.62) v3(75.07,17.9) v3(75.25,48.67) v3(75.2,45.53) v3(75.24,20.32) v3(75.25,9.81) v3(75.37,43.72) v3(75.37,31.66) v3(75.37,13.75) v3(75.37,10.98) v3(75.5,38.9) v3(75.55,19.9) v3(75.63,44.23) v3(75.63,32.16) v3(75.63,31.15) v3(75.64,18.18) v3(75.63,14.26) v3(75.68,47.53) v3(75.74,24.89) v3(75.74,23.62) v3(75.74,21.59) v3(75.75,53.25) v3(75.75,51.98) v3(75.75,49.94) v3(75.77,45.81) v3(75.88,49.31) v3(75.88,48.67) v3(75.88,31.66) v3(75.87,20.95) v3(75.88,9.81) v3(76.01,43.72) v3(76.01,13.75) v3(76.01,10.98) v3(76.14,40.04) v3(76.14,39.53) v3(76.14,38.9) v3(76.09,20.24) v3(76.21,47.87) v3(76.2,18.48) v3(76.32,46.12) v3(76.26,44.23) v3(76.26,30.64) v3(76.26,14.26) v3(76.39,53.25) v3(76.39,51.98) v3(76.39,49.94) v3(76.38,24.89) v3(76.38,23.62) v3(76.38,21.59) v3(76.54,37.45) v3(76.52,9.81) v3(76.64,43.72) v3(76.64,39.78) v3(76.64,39.15) v3(76.61,20.6) v3(76.64,13.75) v3(76.64,10.98) v3(76.64,10.35) v3(76.74,48.24) v3(76.74,18.81) v3(76.87,46.45) v3(76.9,44.23) v3(76.9,14.26) v3(77.02,51.98) v3(77.02,49.94) v3(77.02,30.64) v3(77.01,23.62) v3(77.01,21.59) v3(77.11,20.99) v3(77.24,48.62) v3(77.15,10.73) v3(77.15,10.09) v3(77.28,43.72) v3(77.28,39.78) v3(77.28,39.15) v3(77.27,19.17) v3(77.28,13.75) v3(77.4,46.8) v3(77.53,57.31) v3(77.53,56.68) v3(77.53,56.04) v3(77.53,44.23) v3(77.53,30.01) v3(77.52,28.95) v3(77.52,28.32) v3(77.52,27.68) v3(77.53,14.26) v3(77.65,23.62) v3(77.65,21.59) v3(77.66,51.98) v3(77.66,49.94) v3(77.72,49.04) v3(77.78,19.54) v3(77.91,47.18) v3(77.91,43.72) v3(77.91,13.75) v3(78.18,49.48) v3(78.17,44.23) v3(78.17,14.26) v3(78.29,51.98) v3(78.29,50.2) v3(78.28,23.62) v3(78.28,21.84) v3(78.27,19.94) v3(78.4,47.58) v3(78.55,43.72) v3(78.55,13.75) v3(78.75,20.36) v3(78.8,44.23) v3(78.8,14.26) v3(78.93,51.72) v3(78.88,48) v3(78.93,47.28) v3(78.93,46.64) v3(78.93,46.01) v3(78.93,23.4) v3(78.93,18.58) v3(78.93,17.94) v3(78.93,17.31) v3(79.18,43.72) v3(79.18,13.75) v3(79.29,20.99) v3(79.44,45.5) v3(79.44,44.23) v3(79.44,14.26) v3(79.56,51.72) v3(79.56,23.4) v3(79.56,17.31) v3(79.82,43.72) v3(79.82,39.78) v3(79.82,39.15) v3(79.82,13.75) v3(79.95,10.73) v3(80.07,45.5) v3(80.07,44.23) v3(80.07,14.26) v3(80.2,51.72) v3(80.2,23.4) v3(80.2,17.31) v3(80.2,7.53) v3(80.2,6.89) v3(80.33,10.09) v3(80.45,43.72) v3(80.45,39.78) v3(80.45,39.15) v3(80.45,13.75) v3(80.58,10.73) v3(80.71,45.5) v3(80.71,44.23) v3(80.71,21.88) v3(80.71,14.26) v3(80.83,51.72) v3(80.83,49.69) v3(80.83,23.4) v3(80.83,21.24) v3(80.83,17.31) v3(80.96,38.9) v3(80.96,12.89) v3(80.96,9.84) v3(81.09,47.28) v3(81.09,46.64) v3(81.09,46.01) v3(81.09,43.72) v3(81.09,40.04) v3(81.09,20.48) v3(81.09,19.85) v3(81.09,19.21) v3(81.09,18.58) v3(81.09,17.94) v3(81.09,13.75) v3(81.09,4.99) v3(81.22,50.2) v3(81.22,49.18) v3(81.22,48.55) v3(81.22,47.91) v3(81.22,10.73) v3(81.34,44.99) v3(81.34,44.23) v3(81.34,21.88) v3(81.34,14.26) v3(81.47,51.72) v3(81.47,23.4) v3(81.6,38.9) v3(81.6,12.89) v3(81.6,9.84) v3(81.6,8.31) v3(81.72,46.01) v3(81.72,43.72) v3(81.72,20.86) v3(81.72,18.96) v3(81.72,13.75) v3(81.72,4.99) v3(81.85,49.94) v3(81.85,40.04) v3(81.85,37.37) v3(81.85,10.73) v3(81.98,44.23) v3(81.98,21.88) v3(81.98,14.26) v3(82.1,23.4) v3(82.23,51.6) v3(82.23,49.44) v3(82.23,38.9) v3(82.23,13.11) v3(82.23,9.84) v3(82.23,8.31) v3(82.36,48.67) v3(82.36,48.04) v3(82.36,47.4) v3(82.36,46.77) v3(82.36,46.01) v3(82.36,43.72) v3(82.36,42.45) v3(82.36,41.82) v3(82.36,21.5) v3(82.36,20.86) v3(82.36,18.96) v3(82.36,13.75) v3(82.49,37.37) v3(82.49,12.63) v3(82.49,12) v3(82.49,11.36) v3(82.49,10.73) v3(82.61,44.23) v3(82.61,14.26) v3(82.74,23.66) v3(82.87,38.9) v3(82.87,9.84) v3(82.87,8.31) v3(82.99,51.21) v3(82.99,43.72) v3(82.99,18.96) v3(82.99,13.75) v3(83.12,37.37) v3(83.25,44.23) v3(83.25,14.26) v3(83.37,23.66) v3(83.5,38.9) v3(83.5,9.81) v3(83.5,8.29) v3(83.63,50.58) v3(83.63,43.72) v3(83.63,18.96) v3(83.63,13.75) v3(83.76,37.37) v3(83.88,14.26) v3(84.01,49.82) v3(84.01,23.66) v3(84.14,49.18) v3(84.14,38.9) v3(84.14,9.81) v3(84.14,8.29) v3(84.26,48.42) v3(84.26,47.79) v3(84.26,47.15) v3(84.26,44.36) v3(84.26,23.02) v3(84.26,22.26) v3(84.26,18.96) v3(84.26,17.69) v3(84.26,17.05) v3(84.26,15.78) v3(84.26,15.15) v3(84.26,13.75) v3(84.39,37.37) v3(84.52,14.26) v3(84.77,38.9) v3(84.77,23.66) v3(84.77,19.34) v3(84.77,9.81) v3(84.77,8.29) v3(84.9,48.42) v3(84.9,44.36) v3(84.9,15.15) v3(84.9,13.75) v3(85.03,37.37) v3(85.15,14.26) v3(85.41,38.9) v3(85.41,23.66) v3(85.41,8.29) v3(85.53,48.8) v3(85.53,44.36) v3(85.53,19.34) v3(85.53,15.15) v3(85.53,13.75) v3(85.53,9.94) v3(85.66,37.37) v3(85.79,47.15) v3(85.79,22) v3(85.79,14.26) v3(85.91,40.04) v3(86.04,44.74) v3(86.04,38.9) v3(86.04,23.66) v3(86.04,19.59) v3(86.04,8.42) v3(86.17,48.8) v3(86.17,13.75) v3(86.17,10.19) v3(86.3,47.15) v3(86.3,37.37) v3(86.3,22) v3(86.42,14.26) v3(86.55,40.04) v3(86.55,19.34) v3(86.68,23.66) v3(86.68,8.67) v3(86.8,48.8) v3(86.8,39.02) v3(86.8,13.75) v3(86.8,10.57) v3(86.93,37.37) v3(87.06,14.26) v3(87.31,23.27) v3(87.31,11.08) v3(87.31,8.92) v3(87.44,39.28) v3(87.44,19.34) v3(87.44,13.75) v3(87.69,37.63) v3(87.69,14.26) v3(87.69,11.72) v3(87.82,48.42) v3(87.82,47.79) v3(87.82,47.15) v3(87.82,22.64) v3(87.82,22) v3(87.95,24.29) v3(87.95,14.77) v3(87.95,13.75) v3(87.95,13.11) v3(87.95,12.35) v3(87.95,9.3) v3(88.33,38.01) v3(88.45,9.81) v3(88.84,38.51) v3(88.84,10.45) v3(89.22,39.15) v3(89.22,11.08) v3(89.47,39.78) v3(89.47,32.16) v3(89.47,11.72) v3(89.6,41.05) v3(89.6,40.42) v3(89.6,15.65) v3(89.6,15.02) v3(89.6,14.38) v3(89.6,13.62) v3(89.6,12.99) v3(89.6,12.35) v3(89.72,47.53) v3(89.72,45.5) v3(89.72,44.86) v3(89.72,32.67) v3(89.72,31.66) v3(89.72,24.29) v3(89.72,23.66) v3(89.72,23.02) v3(89.85,42.32) v3(89.85,41.69) v3(89.85,19.21) v3(89.85,18.45) v3(89.85,17.69) v3(89.85,16.92) v3(89.85,16.29) v3(89.98,32.16) v3(90.11,44.23) v3(90.11,22.39) v3(90.11,20.66) v3(90.23,42.96) v3(90.23,32.67) v3(90.23,31.66) v3(90.36,47.53) v3(90.36,45.5) v3(90.49,32.16) v3(90.49,19.59) v3(90.74,32.67) v3(90.74,31.66) v3(90.74,22.39) v3(90.74,20.35) v3(90.99,47.53) v3(90.99,45.5) v3(90.99,32.16) v3(91.25,32.67) v3(91.25,31.66) v3(91.38,22.39) v3(91.38,20.35) v3(91.5,32.16) v3(91.63,47.53) v3(91.63,45.5) v3(91.76,32.67) v3(91.76,31.66) v3(92.01,32.16) v3(92.01,22.39) v3(92.01,20.35) v3(92.26,47.53) v3(92.26,45.5) v3(92.26,32.67) v3(92.26,31.66) v3(92.52,32.16) v3(92.65,22.39) v3(92.65,20.35) v3(92.77,32.67) v3(92.77,31.66) v3(92.9,47.53) v3(92.9,45.5) v3(93.03,32.16) v3(93.28,32.67) v3(93.28,31.66) v3(93.28,22.39) v3(93.28,20.35) v3(93.53,47.53) v3(93.53,45.5) v3(93.53,32.16) v3(93.92,22.39) v3(93.92,20.35) v3(94.17,47.53) v3(94.17,45.5) v3(94.55,22.26) v3(94.55,20.35) v3(94.68,47.4) v3(94.68,45.5) v3(95.19,47.4) v3(95.19,45.5) v3(95.19,22.26) v3(95.19,20.35) v3(95.82,47.4) v3(95.82,45.5) v3(95.82,22.26) v3(95.82,20.35) v3(96.46,47.4) v3(96.46,45.5) v3(96.46,22.26) v3(96.46,20.35) v3(97.09,47.4) v3(97.09,45.5) v3(97.09,22.26) v3(97.09,20.35) v3(97.73,47.4) v3(97.73,45.5) v3(97.73,22.26) v3(97.73,20.35) v3(98.36,47.4) v3(98.36,45.5) v3(98.36,22.26) v3(98.36,20.35) v3(99,47.4) v3(99,45.5) v3(99,22.26) v3(99,20.35) v4(66.89,51.57) v4(66.89,51.01) v4(66.89,50.45) v4(66.89,49.89) v4(66.89,49.33) v4(66.88,23.21) v4(66.88,22.65) v4(66.88,22.1) v4(66.88,21.54) v4(66.88,20.98) v4(67.45,51.57) v4(67.45,51.01) v4(67.45,50.45) v4(67.45,49.89) v4(67.45,49.33) v4(67.44,23.21) v4(67.44,22.65) v4(67.44,22.1) v4(67.44,21.54) v4(67.44,20.98) v4(68.01,51.57) v4(68.01,51.01) v4(68.01,50.45) v4(68.01,49.89) v4(68.01,49.33) v4(68,23.21) v4(68,22.65) v4(68,22.1) v4(68,21.54) v4(68,20.98) v4(68.57,51.57) v4(68.57,51.01) v4(68.57,50.45) v4(68.57,49.89) v4(68.57,49.33) v4(68.56,23.21) v4(68.56,22.65) v4(68.56,22.1) v4(68.56,21.54) v4(68.56,20.98) v4(69.13,51.57) v4(69.13,51.01) v4(69.13,50.45) v4(69.13,49.89) v4(69.13,49.33) v4(69.11,23.21) v4(69.11,22.65) v4(69.11,22.1) v4(69.11,21.54) v4(69.11,20.98) v4(78.18,38.3) v4(78.18,37.39) v4(78.21,9.24) v4(78.21,8.33) v4(78.64,37.84) v4(78.67,8.79) v4(79.1,38.3) v4(79.1,37.39) v4(79.12,9.24) v4(79.12,8.33) v4(84.13,54.1) v4(84.13,52.32) v4(84.14,41.56) v4(84.14,39.78) v4(84.13,27.68) v4(84.13,25.91) v4(84.13,12.32) v4(84.39,10.57) v4(84.64,40.67) v4(85.14,54.1) v4(85.14,52.32) v4(85.14,27.68) v4(85.14,25.91) v4(85.14,12.32) v4(85.15,41.56) v4(85.15,39.78) v4(85.15,10.57)
